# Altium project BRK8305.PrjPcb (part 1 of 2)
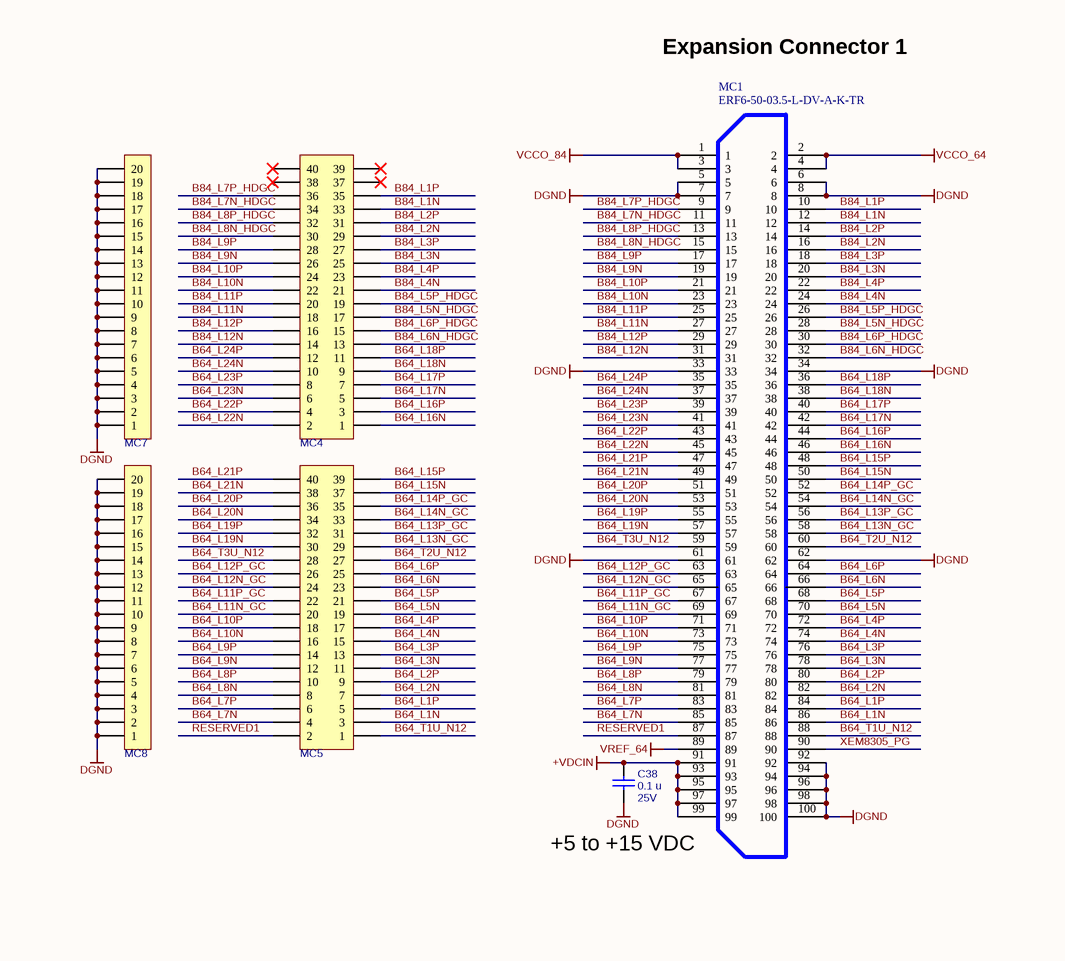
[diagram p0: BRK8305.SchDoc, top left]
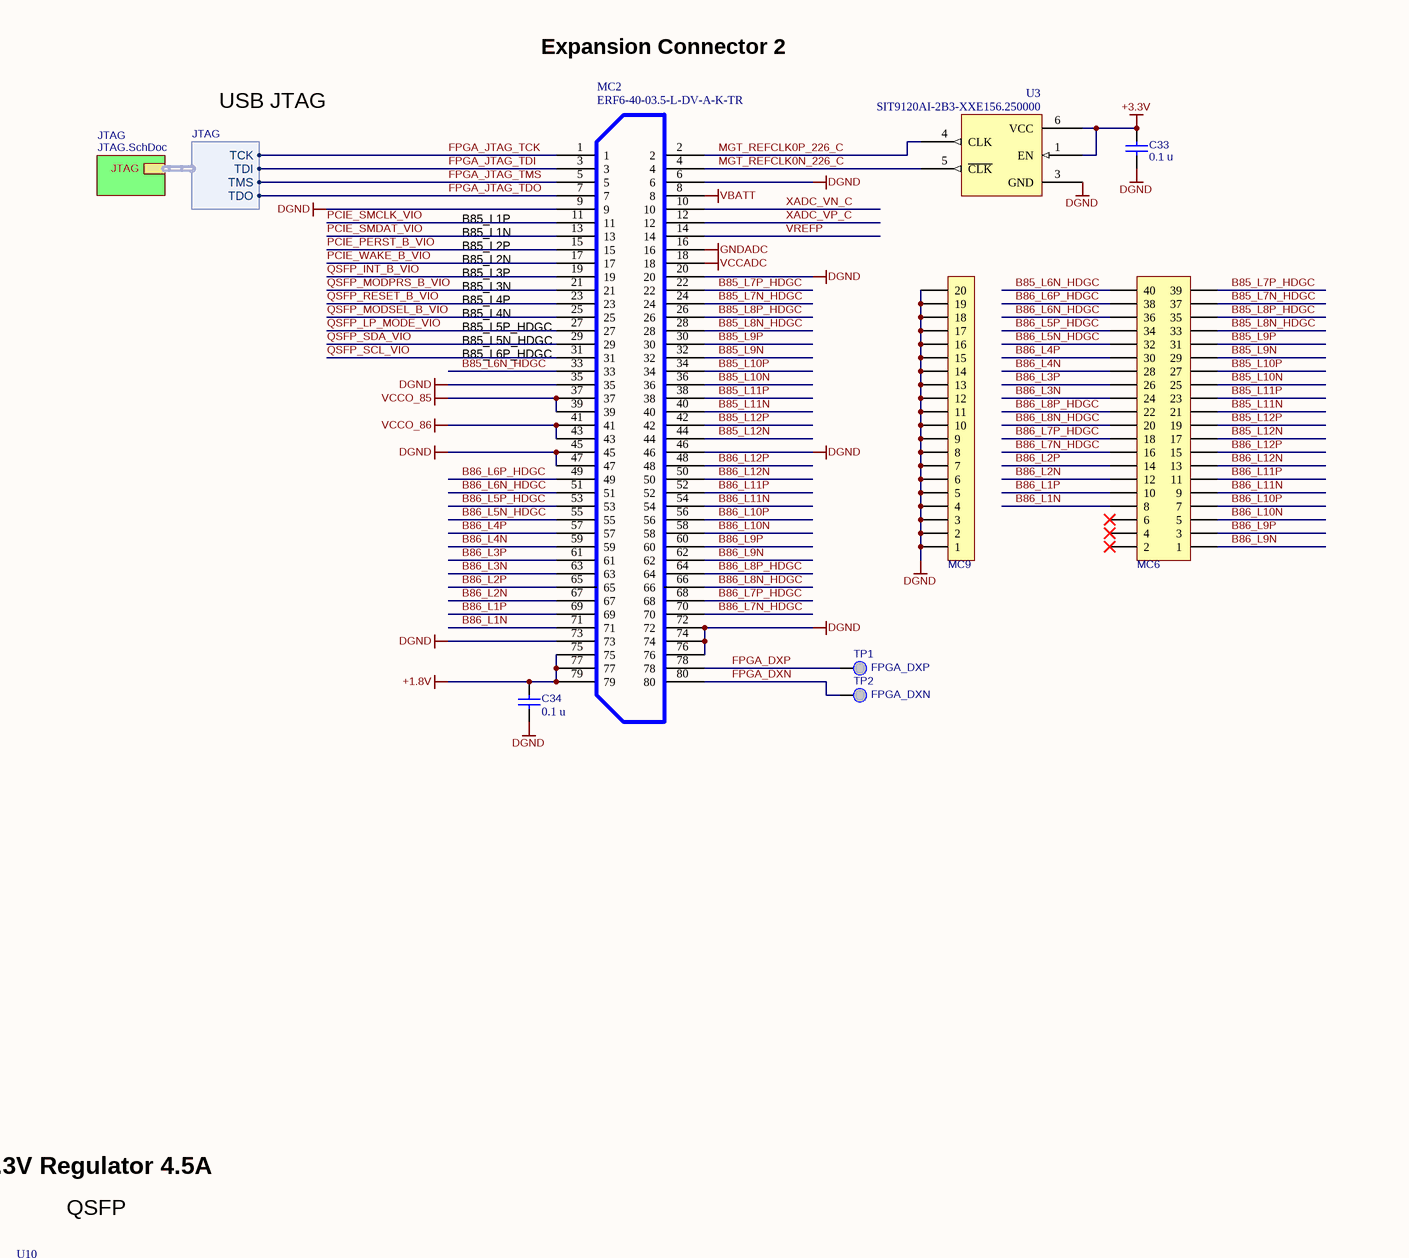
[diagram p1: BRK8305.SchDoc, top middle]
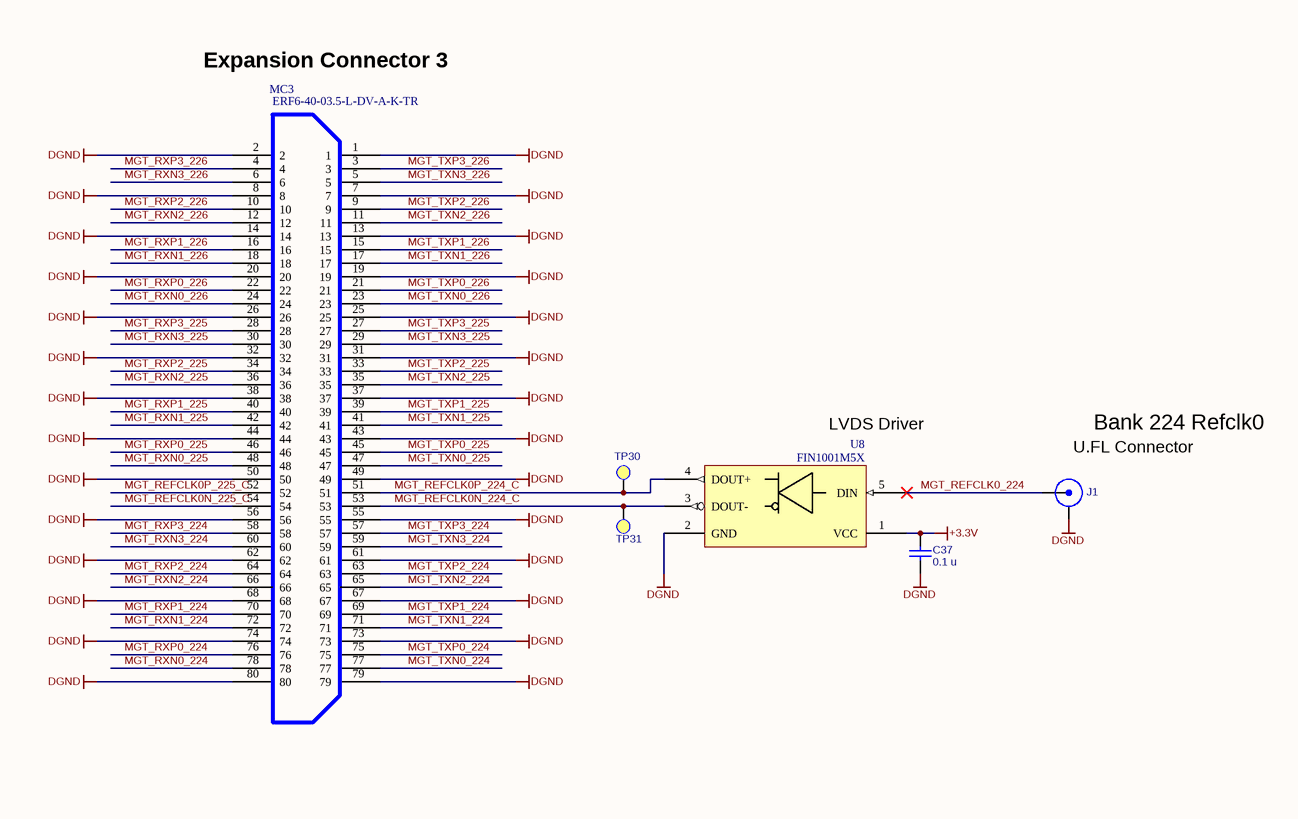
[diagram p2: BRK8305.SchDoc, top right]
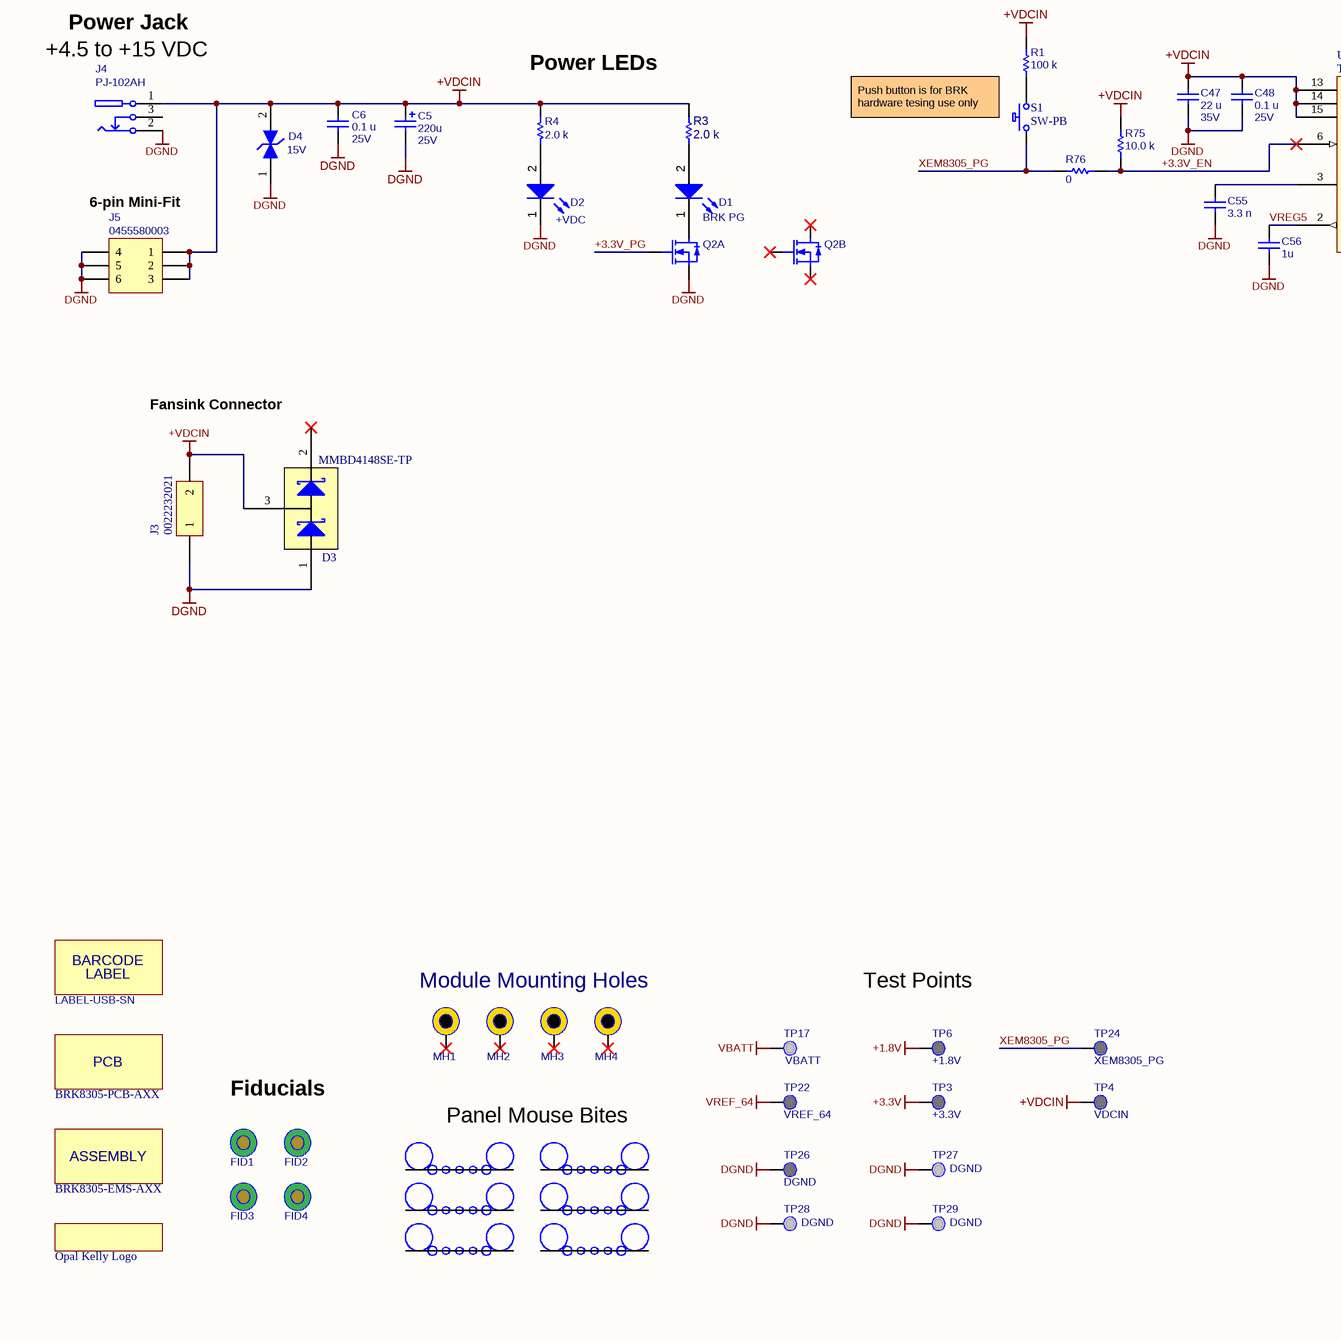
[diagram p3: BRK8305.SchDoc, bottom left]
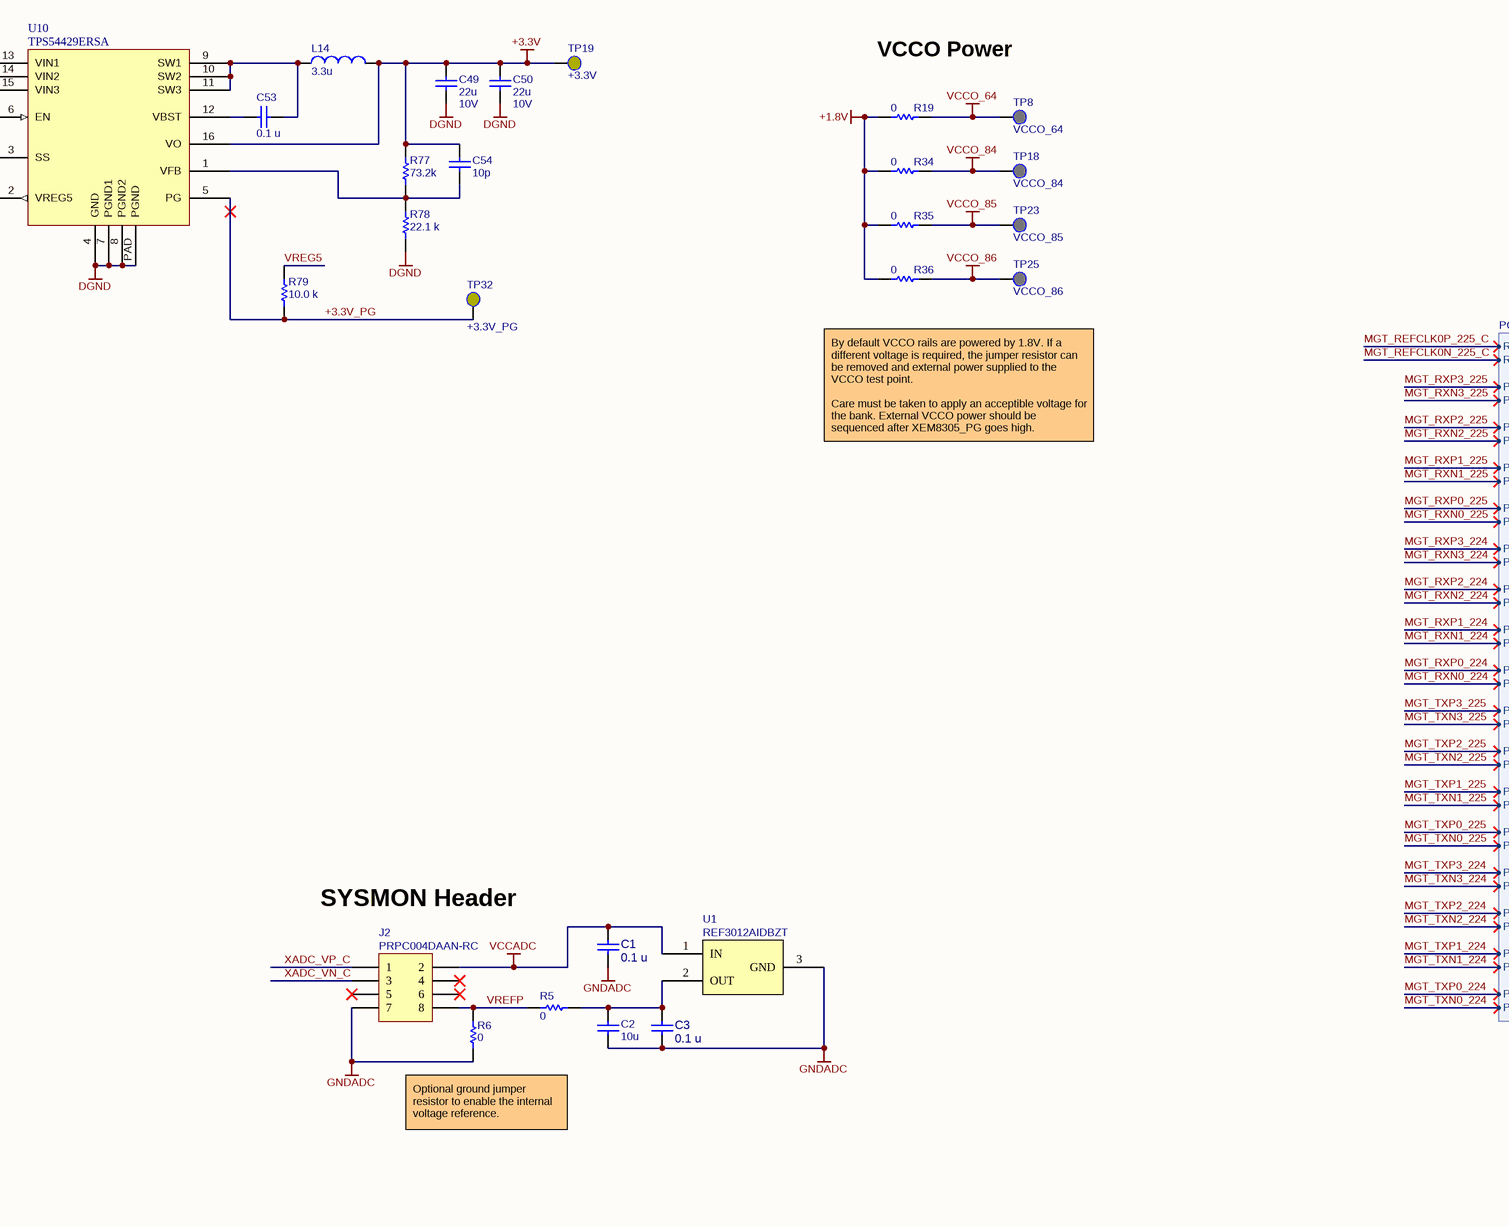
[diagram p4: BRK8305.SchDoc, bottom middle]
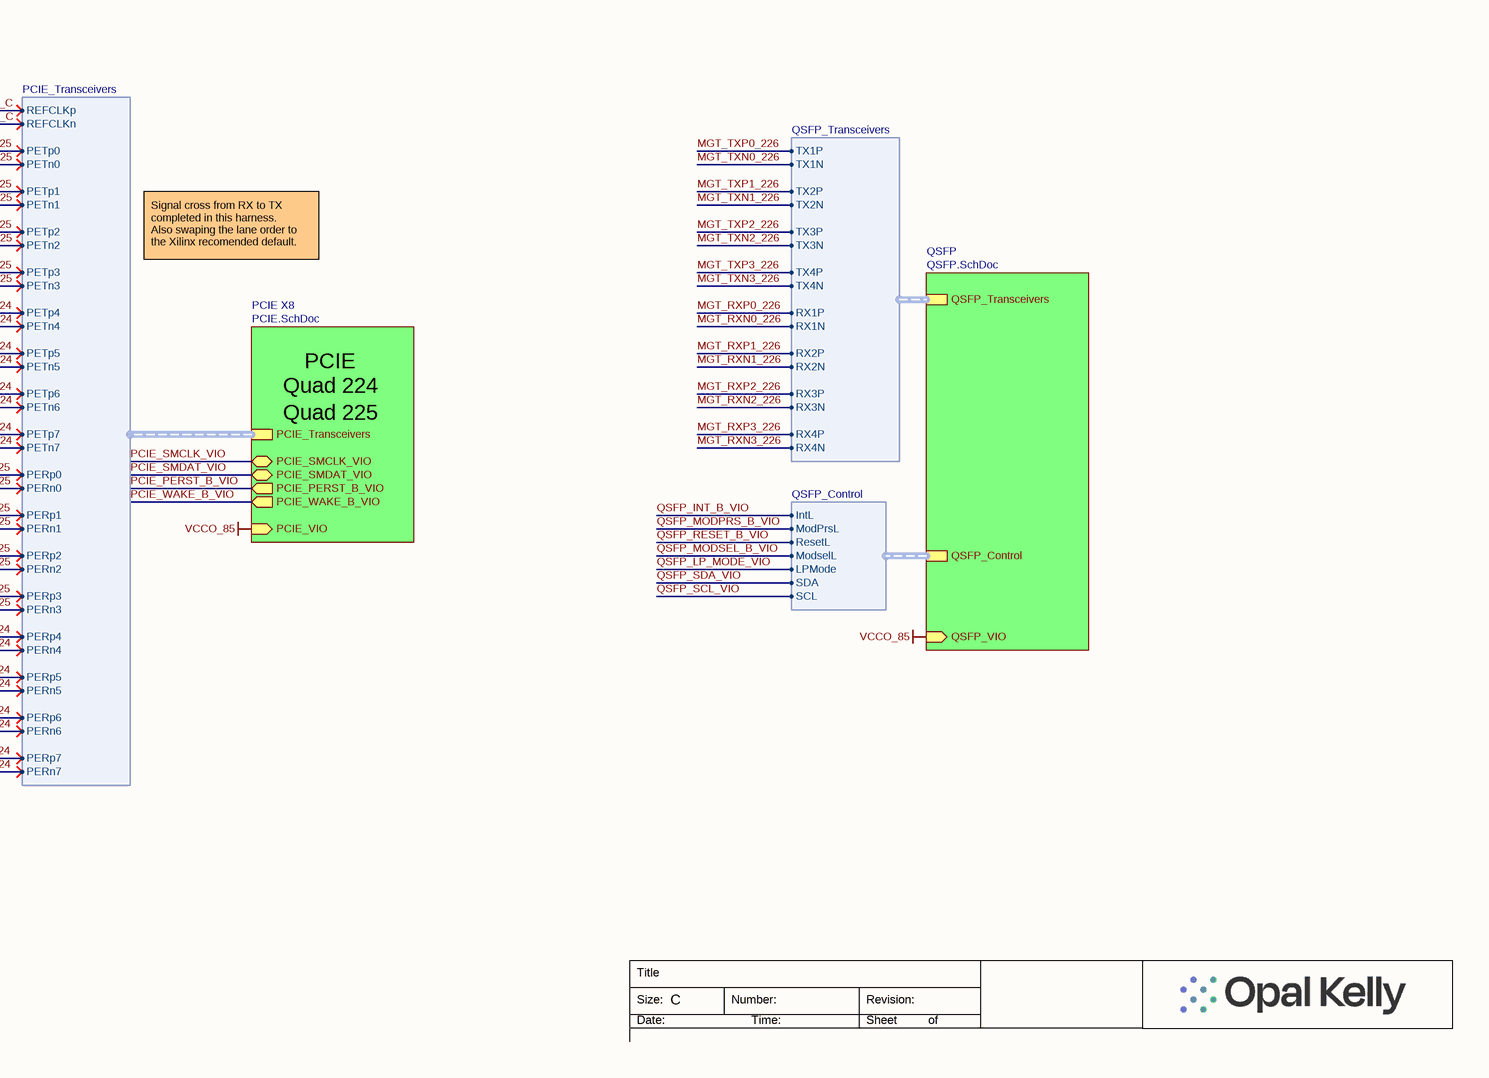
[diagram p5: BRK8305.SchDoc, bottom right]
PCB_Revision: A; Part_Number: BRK8305; BOM_Revision: 03
4 sheets, 240 parts. Net scope: hierarchical (ports join the sheet entries above them; power ports are global).
Board file: BRK8305.PcbDoc
Sheets:
  BRK8305.SchDoc
    PCIE X8 = PCIE.SchDoc
    QSFP = QSFP.SchDoc
    JTAG = JTAG.SchDoc

## Sheet BRK8305.SchDoc: BRK8305 PCB
size D; Author: Ray Anderson; Organization: Opal Kelly; Address1: 13500 SW 72nd Ave, STE 100; Address2: Portland, OR 97223; Address3: 217.391.3724; Address4: http://www.opalkelly.com; DocumentNumber: 1; Revision: 1; SheetNumber: 1; SheetTotal: 3

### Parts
*  Opal Kelly Logo  [okLogo-23x5-2021]
ASSY1  BRK8305-EMS-AXX  (mechanical)
C1  value 0.1 u  [CAPC1005X06A]  (hidden comment: C0402C104K8PACTU)
C2  value 10u  [CAPC1005X06A]  (hidden comment: GRM155C80J106ME11D)
C3  value 0.1 u  [CAPC1005X06A]  (hidden comment: C0402C104K8PACTU)
C5  value 220u  Voltage: 25V  [CAPAE9083X70N]  (hidden comment: EEE-FK1E221P)
C6  value 0.1 u  Voltage: 25V  [CAPC1005X06A]  (hidden comment: TMK105BJ104KV-F)
C33  value 0.1 u  [CAPC1005X06A]  (hidden comment: C0402C104K8PACTU)
C34  value 0.1 u  [CAPC1005X06A]  (hidden comment: C0402C104K8PACTU)
C37  value 0.1 u  [CAPC1005X06A]  (hidden comment: SM-0402, 10%, 10v)
C38  value 0.1 u  Voltage: 25V  [CAPC1005X06A]  (hidden comment: TMK105BJ104KV-F)
C47  value 22 u  Voltage: 35V  [CAPC3216N]  (hidden comment: C3216X5R1V226M160AC)
C48  value 0.1 u  Voltage: 25V  [CAPC1005X06A]  (hidden comment: TMK105BJ104KV-F)
C49  value 22u  Voltage: 10V  [CAPC3216N]  (hidden comment: LMK316AB7226KL-TR)
C50  value 22u  Voltage: 10V  [CAPC3216N]  (hidden comment: LMK316AB7226KL-TR)
C53  value 0.1 u  [CAPC1005X06A]  (hidden comment: C0402C104K8PACTU)
C54  value 10p  [CAPC1005X06A]  (hidden comment: CBR04C100J5GAC)
C55  value 3.3 n  [CAPC1005X06A]  (hidden comment: C0402C332K5RACTU)
C56  value 1u  [CAPC1005X06A]  (hidden comment: LMK105BJ105KV-F)
D1  BRK PG  [CD1608-0603-PIN1-CATHODE]
D2  +VDC  [CD1608-0603-PIN1-CATHODE]
D3  MMBD4148SE-TP  [SOT23-95P240X110]
D4  Voltage: 15V  [DO-214AA]  (hidden comment: D ESD)
FID1  FIDUCIAL  [FID1MM/2MM-SS]  (value not drawn)
FID2  FIDUCIAL  [FID1MM/2MM-SS]  (value not drawn)
FID3  FIDUCIAL  [FID1MM/2MM-SS]  (value not drawn)
FID4  FIDUCIAL  [FID1MM/2MM-SS]  (value not drawn)
J1  RXP0  [UFL-R-SMT-1]  (value not drawn)
J2  PRPC004DAAN-RC  [HDR2X4]
J3  0022232021  [MOLEX-0022232021]
J4  PJ-102AH  [CUI-PJ102A]
J5  0455580003  [0455580003]
L14  value 3.3u  [1267AY]  (hidden comment: 1267AY-3R3N=P3)
LABEL1  LABEL-USB-SN  (mechanical)
MB1  PCB Array Mouse Bite  [MouseBite-01]  (value not drawn)
MB2  PCB Array Mouse Bite  [MouseBite-01]  (value not drawn)
MB3  PCB Array Mouse Bite  [MouseBite-01]  (value not drawn)
MB4  PCB Array Mouse Bite  [MouseBite-01]  (value not drawn)
MB5  PCB Array Mouse Bite  [MouseBite-01]  (value not drawn)
MB6  PCB Array Mouse Bite  [MouseBite-01]  (value not drawn)
MC1  ERF6-50-03.5-L-DV-A-K-TR  [ERF6-50-03.5-L-DV-A-K-TR]
MC2  ERF6-40-03.5-L-DV-A-K-TR  [ERF6-40-03.5-L-DV-A-K-TR]
MC3  ERF6-40-03.5-L-DV-A-K-TR  [ERF6-40-03.5-L-DV-A-K-TR]
MC4  0877584016  [HDR2X20-2MM]  (value not drawn)
MC5  0877584016  [HDR2X20-2MM]  (value not drawn)
MC6  0877584016  [HDR2X20-2MM]  (value not drawn)
MC7  Header, 20-Pin, Single Row  [HDR1X20-2MM]  (value not drawn)
MC8  Header, 20-Pin, Single Row  [HDR1X20-2MM]  (value not drawn)
MC9  Header, 20-Pin, Single Row  [HDR1X20-2MM]  (value not drawn)
MH1  MTG  [MTG-3.2/6.5-PTH]  (value not drawn)
MH2  MTG  [MTG-3.2/6.5-PTH]  (value not drawn)
MH3  MTG  [MTG-3.2/6.5-PTH]  (value not drawn)
MH4  MTG  [MTG-3.2/6.5-PTH]  (value not drawn)
PCB1  BRK8305-PCB-AXX  (mechanical)
Q2  SI1922EDH-T1-GE3  [SOT363-6N]  (value not drawn)  (parts A,B of 2)
R1  value 100 k  [RESC1005X06A]  (hidden comment: CRCW0402100KFKED)
R3  value 2.0 k  [RESC1005X06A]  (hidden comment: CRCW04022K00FKED)
R4  value 2.0 k  [RESC1005X06A]  (hidden comment: CRCW04022K00FKED)
R5  value 0  [RESC1608N]  (hidden comment: CRCW06030000Z0EA)
R6  value 0  [RESC1608N]  (hidden comment: CRCW06030000Z0EA)
R19  value 0  [RESC1608N]  (hidden comment: CRCW06030000Z0EA)
R34  value 0  [RESC1608N]  (hidden comment: CRCW06030000Z0EA)
R35  value 0  [RESC1608N]  (hidden comment: CRCW06030000Z0EA)
R36  value 0  [RESC1608N]  (hidden comment: CRCW06030000Z0EA)
R75  value 10.0 k  [RESC1005X06A]  (hidden comment: CRCW040210K0FKED)
R76  value 0  [RESC1005X06A]  (hidden comment: CRCW04020000Z0ED)
R77  value 73.2k  [RESC1005X06A]  (hidden comment: CRCW040273K2FKED)
R78  value 22.1 k  [RESC1005X06A]  (hidden comment: CRCW040222K1FKEDC)
R79  value 10.0 k  [RESC1005X06A]  (hidden comment: CRCW040210K0FKED)
S1  SW-PB  [Switch-PCB-wMounts]
TP1  FPGA_DXP  [TP-PTH-25/45]
TP2  FPGA_DXN  [TP-PTH-25/45]
TP3  +3.3V  [TP-PTH-65/100]
TP4  VDCIN  [TP-PTH-65/100]
TP6  +1.8V  [TP-PTH-65/100]
TP8  VCCO_64  [TP-PTH-65/100]
TP17  VBATT  [TP-PTH-25/45]
TP18  VCCO_84  [TP-PTH-65/100]
TP19  +3.3V  [TP-SMD40]
TP22  VREF_64  [TP-PTH-65/100]
TP23  VCCO_85  [TP-PTH-65/100]
TP24  XEM8305_PG  [TP-PTH-65/100]
TP25  VCCO_86  [TP-PTH-65/100]
TP26  DGND  [TP-PTH-65/100]
TP27  DGND  [TP-PTH-25/45]
TP28  DGND  [TP-PTH-25/45]
TP29  DGND  [TP-PTH-25/45]
TP30  TESTPOINT-SMD20  [TP-SMD20]  (value not drawn)
TP31  TESTPOINT-SMD20  [TP-SMD20]  (value not drawn)
TP32  +3.3V_PG  [TP-SMD40]
U1  REF3012AIDBZT  [SOT23-95P240X110]
U3  SIT9120AI-2B3-XXE156.250000  [SIT9120AX-XB]
U8  FIN1001M5X  [SOT23-5]
U10  TPS54429ERSA  [TPS54429E]

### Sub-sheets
JTAG = JTAG.SchDoc: JTAG (harness JTAG)
PCIE X8 = PCIE.SchDoc: PCIE_Transceivers (harness PCIE_Transceivers), PCIE_SMCLK_VIO (bidir), PCIE_WAKE_B_VIO (out), PCIE_SMDAT_VIO (bidir), PCIE_PERST_B_VIO (out), PCIE_VIO (in)
QSFP = QSFP.SchDoc: QSFP_Control (harness QSFP_Control), QSFP_Transceivers (harness QSFP_Transceivers), QSFP_VIO (in)

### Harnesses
PCIE_Transceivers: PETn3, PETp3, PERn3, PERp3, PETn2, PETp2, PERn2, PERp2, PETn1, PETp1, PERn1, PERp1, PETn0, PETp0, PERn0, PERp0, PETn4, PETp4, PERn4, PERp4, PETn5, PETp5, PERn5, PERp5, PETn6, PETp6, PERn6, PERp6, PETn7, PETp7, PERn7, PERp7, REFCLKn, REFCLKp
QSFP_Transceivers: TX1P, TX1N, TX2P, TX2N, TX3P, TX3N, TX4P, TX4N, RX1P, RX1N, RX2P, RX2N, RX3P, RX3N, RX4P, RX4N
QSFP_Control: ModPrsL, IntL, LPMode, ModselL, ResetL, SCL, SDA
JTAG: TDI, TDO, TCK, TMS

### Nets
+1.8V: C34.2 MC2.75 MC2.77 MC2.79 R19.1 R34.1 R35.1 R36.1 TP6.1(PIN)
+3.3V: C33.2 C37.2 C49.2 C50.2 C54.2 L14.2 R77.2 TP3.1(PIN) TP19.1(PIN) U3.1(EN) U3.6(VCC) U8.1(VCC) U10.16(VO)
+VDCIN: C5.1 C6.2 C38.2 C47.2 C48.2 D3.3 D4.2(K) J3.2 J4.1 J5.1 J5.2 J5.3 MC1.91 MC1.93 MC1.95 MC1.97 MC1.99 R1.2 R3.2 R4.2 R75.2 TP4.1(PIN) U10.13(VIN1) U10.14(VIN2) U10.15(VIN3)
DGND: C5.2 C6.1 C33.1 C34.1 C37.1 C38.1 C47.1 C48.1 C49.1 C50.1 C55.1 C56.1 D2.1(K) D3.1 D4.1(A) J1.2(GND) J3.1 J4.2 J5.4 J5.5 J5.6 MC1.5 MC1.6 MC1.7 MC1.8 MC1.33 MC1.34 MC1.61 MC1.62 MC1.92 MC1.94 MC1.96 MC1.98 MC1.100 MC2.6 MC2.9 MC2.20 MC2.35 MC2.45 MC2.46 MC2.47 MC2.72 MC2.73 MC2.74 MC2.76 MC3.1 MC3.2 MC3.7 MC3.8 MC3.13 MC3.14 MC3.19 MC3.20 MC3.25 MC3.26 MC3.31 MC3.32 MC3.37 MC3.38 MC3.43 MC3.44 MC3.49 MC3.50 MC3.55 MC3.56 MC3.61 MC3.62 MC3.67 MC3.68 MC3.73 MC3.74 MC3.79 MC3.80 MC7.1 MC7.2 MC7.3 MC7.4 MC7.5 MC7.6 MC7.7 MC7.8 MC7.9 MC7.10 MC7.11 MC7.12 MC7.13 MC7.14 MC7.15 MC7.16 MC7.17 MC7.18 MC7.19 MC7.20 MC8.1 MC8.2 MC8.3 MC8.4 MC8.5 MC8.6 MC8.7 MC8.8 MC8.9 MC8.10 MC8.11 MC8.12 MC8.13 MC8.14 MC8.15 MC8.16 MC8.17 MC8.18 MC8.19 MC8.20 MC9.1 MC9.2 MC9.3 MC9.4 MC9.5 MC9.6 MC9.7 MC9.8 MC9.9 MC9.10 MC9.11 MC9.12 MC9.13 MC9.14 MC9.15 MC9.16 MC9.17 MC9.18 MC9.19 MC9.20 Q2.1(S1) R78.1 TP26.1(PIN) TP27.1(PIN) TP28.1(PIN) TP29.1(PIN) U3.3(GND) U8.2(GND) U10.4(GND) U10.7(PGND1) U10.8(PGND2) U10.PAD(PGND)
GNDADC: C1.2 C2.1 C3.2 J2.7 MC2.16 R6.1 U1.3(GND)
VBATT: MC2.8 TP17.1(PIN)
VCCADC: C1.1 J2.2 MC2.18 U1.1(IN)
VCCO_64: MC1.2 MC1.4 R19.2 TP8.1(PIN)
VCCO_84: MC1.1 MC1.3 R34.2 TP18.1(PIN)
VCCO_85: MC2.37 MC2.39 R35.2 TP23.1(PIN) ; sheet PCIE X8/PCIE_VIO, sheet QSFP/QSFP_VIO
VCCO_86: MC2.41 MC2.43 R36.2 TP25.1(PIN)
VREF_64: MC1.89 TP22.1(PIN)
+3.3V_EN: R75.1 R76.1 U10.6(EN)
+3.3V_PG: Q2.2(G1) R79.1 TP32.1(PIN) U10.5(PG)
B64_L1N: MC1.86 MC5.3
B64_L1P: MC1.84 MC5.5
B64_L2N: MC1.82 MC5.7
B64_L2P: MC1.80 MC5.9
B64_L3N: MC1.78 MC5.11
B64_L3P: MC1.76 MC5.13
B64_L4N: MC1.74 MC5.15
B64_L4P: MC1.72 MC5.17
B64_L5N: MC1.70 MC5.19
B64_L5P: MC1.68 MC5.21
B64_L6N: MC1.66 MC5.23
B64_L6P: MC1.64 MC5.25
B64_L7N: MC1.85 MC5.4
B64_L7P: MC1.83 MC5.6
B64_L8N: MC1.81 MC5.8
B64_L8P: MC1.79 MC5.10
B64_L9N: MC1.77 MC5.12
B64_L9P: MC1.75 MC5.14
B64_L10N: MC1.73 MC5.16
B64_L10P: MC1.71 MC5.18
B64_L11N_GC: MC1.69 MC5.20
B64_L11P_GC: MC1.67 MC5.22
B64_L12N_GC: MC1.65 MC5.24
B64_L12P_GC: MC1.63 MC5.26
B64_L13N_GC: MC1.58 MC5.29
B64_L13P_GC: MC1.56 MC5.31
B64_L14N_GC: MC1.54 MC5.33
B64_L14P_GC: MC1.52 MC5.35
B64_L15N: MC1.50 MC5.37
B64_L15P: MC1.48 MC5.39
B64_L16N: MC1.46 MC4.1
B64_L16P: MC1.44 MC4.3
B64_L17N: MC1.42 MC4.5
B64_L17P: MC1.40 MC4.7
B64_L18N: MC1.38 MC4.9
B64_L18P: MC1.36 MC4.11
B64_L19N: MC1.57 MC5.30
B64_L19P: MC1.55 MC5.32
B64_L20N: MC1.53 MC5.34
B64_L20P: MC1.51 MC5.36
B64_L21N: MC1.49 MC5.38
B64_L21P: MC1.47 MC5.40
B64_L22N: MC1.45 MC4.2
B64_L22P: MC1.43 MC4.4
B64_L23N: MC1.41 MC4.6
B64_L23P: MC1.39 MC4.8
B64_L24N: MC1.37 MC4.10
B64_L24P: MC1.35 MC4.12
B64_T1U_N12: MC1.88 MC5.1
B64_T2U_N12: MC1.60 MC5.27
B64_T3U_N12: MC1.59 MC5.28
B84_L1N: MC1.12 MC4.33
B84_L1P: MC1.10 MC4.35
B84_L2N: MC1.16 MC4.29
B84_L2P: MC1.14 MC4.31
B84_L3N: MC1.20 MC4.25
B84_L3P: MC1.18 MC4.27
B84_L4N: MC1.24 MC4.21
B84_L4P: MC1.22 MC4.23
B84_L5N_HDGC: MC1.28 MC4.17
B84_L5P_HDGC: MC1.26 MC4.19
B84_L6N_HDGC: MC1.32 MC4.13
B84_L6P_HDGC: MC1.30 MC4.15
B84_L7N_HDGC: MC1.11 MC4.34
B84_L7P_HDGC: MC1.9 MC4.36
B84_L8N_HDGC: MC1.15 MC4.30
B84_L8P_HDGC: MC1.13 MC4.32
B84_L9N: MC1.19 MC4.26
B84_L9P: MC1.17 MC4.28
B84_L10N: MC1.23 MC4.22
B84_L10P: MC1.21 MC4.24
B84_L11N: MC1.27 MC4.18
B84_L11P: MC1.25 MC4.20
B84_L12N: MC1.31 MC4.14
B84_L12P: MC1.29 MC4.16
B85_L6N_HDGC: MC2.33 MC6.40
B85_L7N_HDGC: MC2.24 MC6.37
B85_L7P_HDGC: MC2.22 MC6.39
B85_L8N_HDGC: MC2.28 MC6.33
B85_L8P_HDGC: MC2.26 MC6.35
B85_L9N: MC2.32 MC6.29
B85_L9P: MC2.30 MC6.31
B85_L10N: MC2.36 MC6.25
B85_L10P: MC2.34 MC6.27
B85_L11N: MC2.40 MC6.21
B85_L11P: MC2.38 MC6.23
B85_L12N: MC2.44 MC6.17
B85_L12P: MC2.42 MC6.19
B86_L1N: MC2.71 MC6.8
B86_L1P: MC2.69 MC6.10
B86_L2N: MC2.67 MC6.12
B86_L2P: MC2.65 MC6.14
B86_L3N: MC2.63 MC6.24
B86_L3P: MC2.61 MC6.26
B86_L4N: MC2.59 MC6.28
B86_L4P: MC2.57 MC6.30
B86_L5N_HDGC: MC2.55 MC6.32
B86_L5P_HDGC: MC2.53 MC6.34
B86_L6N_HDGC: MC2.51 MC6.36
B86_L6P_HDGC: MC2.49 MC6.38
B86_L7N_HDGC: MC2.70 MC6.16
B86_L7P_HDGC: MC2.68 MC6.18
B86_L8N_HDGC: MC2.66 MC6.20
B86_L8P_HDGC: MC2.64 MC6.22
B86_L9N: MC2.62 MC6.1
B86_L9P: MC2.60 MC6.3
B86_L10N: MC2.58 MC6.5
B86_L10P: MC2.56 MC6.7
B86_L11N: MC2.54 MC6.9
B86_L11P: MC2.52 MC6.11
B86_L12N: MC2.50 MC6.13
B86_L12P: MC2.48 MC6.15
FPGA_DXN: MC2.80 TP2.1(PIN)
FPGA_DXP: MC2.78 TP1.1(PIN)
FPGA_JTAG_TCK: MC2.1 ; sheet JTAG/JTAG.TCK
FPGA_JTAG_TDI: MC2.3 ; sheet JTAG/JTAG.TDI
FPGA_JTAG_TDO: MC2.7 ; sheet JTAG/JTAG.TDO
FPGA_JTAG_TMS: MC2.5 ; sheet JTAG/JTAG.TMS
MGT_REFCLK0_224: J1.1(SIGNAL) U8.5(DIN)
MGT_REFCLK0N_224_C: MC3.53 TP31.1(PIN) U8.3(DOUT-)
MGT_REFCLK0N_225_C: MC3.54 ; sheet PCIE X8/PCIE_Transceivers.REFCLKn
MGT_REFCLK0N_226_C: MC2.4 U3.5(~{CLK})
MGT_REFCLK0P_224_C: MC3.51 TP30.1(PIN) U8.4(DOUT+)
MGT_REFCLK0P_225_C: MC3.52 ; sheet PCIE X8/PCIE_Transceivers.REFCLKp
MGT_REFCLK0P_226_C: MC2.2 U3.4(CLK)
MGT_RXN0_224: MC3.78 ; sheet PCIE X8/PCIE_Transceivers.PETn7
MGT_RXN0_225: MC3.48 ; sheet PCIE X8/PCIE_Transceivers.PETn3
MGT_RXN0_226: MC3.24 ; sheet QSFP/QSFP_Transceivers.RX1N
MGT_RXN1_224: MC3.72 ; sheet PCIE X8/PCIE_Transceivers.PETn6
MGT_RXN1_225: MC3.42 ; sheet PCIE X8/PCIE_Transceivers.PETn2
MGT_RXN1_226: MC3.18 ; sheet QSFP/QSFP_Transceivers.RX2N
MGT_RXN2_224: MC3.66 ; sheet PCIE X8/PCIE_Transceivers.PETn5
MGT_RXN2_225: MC3.36 ; sheet PCIE X8/PCIE_Transceivers.PETn1
MGT_RXN2_226: MC3.12 ; sheet QSFP/QSFP_Transceivers.RX3N
MGT_RXN3_224: MC3.60 ; sheet PCIE X8/PCIE_Transceivers.PETn4
MGT_RXN3_225: MC3.30 ; sheet PCIE X8/PCIE_Transceivers.PETn0
MGT_RXN3_226: MC3.6 ; sheet QSFP/QSFP_Transceivers.RX4N
MGT_RXP0_224: MC3.76 ; sheet PCIE X8/PCIE_Transceivers.PETp7
MGT_RXP0_225: MC3.46 ; sheet PCIE X8/PCIE_Transceivers.PETp3
MGT_RXP0_226: MC3.22 ; sheet QSFP/QSFP_Transceivers.RX1P
MGT_RXP1_224: MC3.70 ; sheet PCIE X8/PCIE_Transceivers.PETp6
MGT_RXP1_225: MC3.40 ; sheet PCIE X8/PCIE_Transceivers.PETp2
MGT_RXP1_226: MC3.16 ; sheet QSFP/QSFP_Transceivers.RX2P
MGT_RXP2_224: MC3.64 ; sheet PCIE X8/PCIE_Transceivers.PETp5
MGT_RXP2_225: MC3.34 ; sheet PCIE X8/PCIE_Transceivers.PETp1
MGT_RXP2_226: MC3.10 ; sheet QSFP/QSFP_Transceivers.RX3P
MGT_RXP3_224: MC3.58 ; sheet PCIE X8/PCIE_Transceivers.PETp4
MGT_RXP3_225: MC3.28 ; sheet PCIE X8/PCIE_Transceivers.PETp0
MGT_RXP3_226: MC3.4 ; sheet QSFP/QSFP_Transceivers.RX4P
MGT_TXN0_224: MC3.77 ; sheet PCIE X8/PCIE_Transceivers.PERn7
MGT_TXN0_225: MC3.47 ; sheet PCIE X8/PCIE_Transceivers.PERn3
MGT_TXN0_226: MC3.23 ; sheet QSFP/QSFP_Transceivers.TX1N
MGT_TXN1_224: MC3.71 ; sheet PCIE X8/PCIE_Transceivers.PERn6
MGT_TXN1_225: MC3.41 ; sheet PCIE X8/PCIE_Transceivers.PERn2
MGT_TXN1_226: MC3.17 ; sheet QSFP/QSFP_Transceivers.TX2N
MGT_TXN2_224: MC3.65 ; sheet PCIE X8/PCIE_Transceivers.PERn5
MGT_TXN2_225: MC3.35 ; sheet PCIE X8/PCIE_Transceivers.PERn1
MGT_TXN2_226: MC3.11 ; sheet QSFP/QSFP_Transceivers.TX3N
MGT_TXN3_224: MC3.59 ; sheet PCIE X8/PCIE_Transceivers.PERn4
MGT_TXN3_225: MC3.29 ; sheet PCIE X8/PCIE_Transceivers.PERn0
MGT_TXN3_226: MC3.5 ; sheet QSFP/QSFP_Transceivers.TX4N
MGT_TXP0_224: MC3.75 ; sheet PCIE X8/PCIE_Transceivers.PERp7
MGT_TXP0_225: MC3.45 ; sheet PCIE X8/PCIE_Transceivers.PERp3
MGT_TXP0_226: MC3.21 ; sheet QSFP/QSFP_Transceivers.TX1P
MGT_TXP1_224: MC3.69 ; sheet PCIE X8/PCIE_Transceivers.PERp6
MGT_TXP1_225: MC3.39 ; sheet PCIE X8/PCIE_Transceivers.PERp2
MGT_TXP1_226: MC3.15 ; sheet QSFP/QSFP_Transceivers.TX2P
MGT_TXP2_224: MC3.63 ; sheet PCIE X8/PCIE_Transceivers.PERp5
MGT_TXP2_225: MC3.33 ; sheet PCIE X8/PCIE_Transceivers.PERp1
MGT_TXP2_226: MC3.9 ; sheet QSFP/QSFP_Transceivers.TX3P
MGT_TXP3_224: MC3.57 ; sheet PCIE X8/PCIE_Transceivers.PERp4
MGT_TXP3_225: MC3.27 ; sheet PCIE X8/PCIE_Transceivers.PERp0
MGT_TXP3_226: MC3.3 ; sheet QSFP/QSFP_Transceivers.TX4P
PCIE_PERST_B_VIO: MC2.15 ; sheet PCIE X8/PCIE_PERST_B_VIO
PCIE_SMCLK_VIO: MC2.11 ; sheet PCIE X8/PCIE_SMCLK_VIO
PCIE_SMDAT_VIO: MC2.13 ; sheet PCIE X8/PCIE_SMDAT_VIO
PCIE_WAKE_B_VIO: MC2.17 ; sheet PCIE X8/PCIE_WAKE_B_VIO
QSFP_INT_B_VIO: MC2.19 ; sheet QSFP/QSFP_Control.IntL
QSFP_LP_MODE_VIO: MC2.27 ; sheet QSFP/QSFP_Control.LPMode
QSFP_MODPRS_B_VIO: MC2.21 ; sheet QSFP/QSFP_Control.ModPrsL
QSFP_MODSEL_B_VIO: MC2.25 ; sheet QSFP/QSFP_Control.ModselL
QSFP_RESET_B_VIO: MC2.23 ; sheet QSFP/QSFP_Control.ResetL
QSFP_SCL_VIO: MC2.31 ; sheet QSFP/QSFP_Control.SCL
QSFP_SDA_VIO: MC2.29 ; sheet QSFP/QSFP_Control.SDA
RESERVED1: MC1.87 MC5.2
VREFP: J2.8 MC2.14 R5.2 R6.2
VREG5: C56.2 R79.2 U10.2(VREG5)
XADC_VN_C: J2.3 MC2.10
XADC_VP_C: J2.1 MC2.12
XEM8305_PG: MC1.90 R76.2 S1.1 TP24.1(PIN)
NetC2_2: C2.2 C3.1 R5.1 U1.2(OUT)
NetC53_1: C53.1 U10.12(VBST)
NetC53_2: C53.2 L14.1 U10.9(SW1) U10.10(SW2) U10.11(SW3)
NetC54_1: C54.1 R77.1 R78.2 U10.1(VFB)
NetC55_2: C55.2 U10.3(SS)
NetD1_1: D1.1(K) Q2.6(D1)
NetD1_2: D1.2(A) R3.1
NetD2_2: D2.2(A) R4.1
NetR1_1: R1.1 S1.2

Not connected (* = marked no-connect by the designer): D3 2*; J2 4* 5* 6*; J4 3; MC4 37* 38* 39* 40*; MC6 2* 4* 6*; MH1 1*; MH2 1*; MH3 1*; MH4 1*; Q2 3(D2)* 4(S2)* 5(G2)*

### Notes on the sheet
- Expansion Connector 1
- Expansion Connector 2
- Expansion Connector 3
- USB JTAG
- (near MC2) B85_L1P
  B85_L1N
  B85_L2P
  B85_L2N
  B85_L3P
  B85_L3N
  B85_L4P
  B85_L4N
  B85_L5P_HDGC
  B85_L5N_HDGC
  B85_L6P_HDGC
- (near U8) LVDS Driver
- (near J1) U.FL Connector
- Bank 224 Refclk0
- +5 to +15 VDC
- 3.3V Regulator 4.5A
- QSFP
- Power Jack
- (near J4) +4.5 to +15 VDC
- Power LEDs
- VCCO Power
- Push button is for BRK hardware tesing use only
- 6-pin Mini-Fit
- Fansink Connector
- By default VCCO rails are powered by 1.8V. If a different voltage is required, the jumper resistor can be removed and external power supplied to the VCCO test point.
  Care must be taken to apply an acceptible voltage for the bank. External VCCO power should be sequenced after XEM8305_PG goes high.
- Signal cross from RX to TX completed in this harness.
  Also swaping the lane order to the Xilinx recomended default.
- Quad 224
- Quad 225
- PCIE
- SYSMON Header
- Module Mounting Holes
- Test Points
- Fiducials
- (near MB2) Panel Mouse Bites
- (near R6) Optional ground jumper resistor to enable the internal voltage reference.
- Title
- Size:
- Date:
- C
- Number:
- Time:
- Revision:
- Sheet
- of

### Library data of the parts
* = OKLOGO: partnumber: ALIGNI_IGNORE
ASSY1 = 002591: BRK8305 PCB assembly; Partnumber: 002591; Manufacturer: PCB Assembly Cost
C1 C3 = 000070: Ceramic capacitor; Manufacturer: Kemet; partnumber: 000070; Description 2: SM-0402, 10%, 10v; ValueFloat: 1E-7; Tolerance (%): 10
C2 = 001983: Ceramic capacitor; Partnumber: 001983; Manufacturer: Murata; ValueFloat: 1E-5; Tolerance (%): 20; Description 2: 0402, 6.3V
C5 = 001532: Polarized; Partnumber: 001532; manufacturer: Panasonic; ValueFloat: 0.00022; id: 155442; inventory_price: 0.2; x_tolerance: 20; x_voltage-rating: 25
C6 C38 = 001073: Ceramic capacitor; Manufacturer: Taiyo Yuden; partnumber: 001073; Description 2: 0402, 25V; ValueFloat: 1E-7; Tolerance (%): 10
C33 C53 = 000070: Partnumber: 000070; manufacturer: Kemet; ValueFloat: 1E-7; x_tolerance: 10
C34 = 000070: Ceramic capacitor; Partnumber: 000070; Manufacturer: Kemet; ValueFloat: 1E-7; Tolerance (%): 10; Description 2: SM-0402, 10%, 10v
C37 = 000070: Partnumber: 000070; manufacturer: Kemet; manufacturer_pn: C0402C104K8PACTU; ValueFloat: 1E-7; id: 750; inventory_price: 0.0023; reorder_quantity: 70000; x_tolerance: 10
C47 = 001172: Partnumber: 001172; manufacturer: TDK; ValueFloat: 2.2E-5; x_tolerance: 20; x_voltage-rating: 35
C48 = 001073: Partnumber: 001073; manufacturer: Taiyo Yuden; ValueFloat: 1E-7; x_tolerance: 10
C49 C50 = 001284: Partnumber: 001284; manufacturer: Taiyo Yuden; ValueFloat: 2.2E-5; x_tolerance: 10
C54 = 001297: Partnumber: 001297; manufacturer: Kemet; ValueFloat: 1E-11; x_tolerance: 5; x_voltage-rating: 50
C55 = 001277: Partnumber: 001277; manufacturer: Kemet; ValueFloat: 3.3E-9; x_tolerance: 10; x_voltage-rating: 50
C56 = 000480: Partnumber: 000480; manufacturer: Taiyo Yuden; ValueFloat: 1E-6; x_tolerance: 10
D1 D2 = 001433: LED; Manufacturer: Dialight; Manufacturer_PN: 598-8070-107F; partnumber: 001433; Description 2: SM-0603, green; x_lifecycle_status: Production
D3 = 002130: High Conductance, Ultra Fast Diode; Partnumber: 002130; Manufacturer: Micro Commercial Co; Description 2: 100V 350MA SOT23
D4 = 002129: Transient Voltage Suppressor; Manufacturer: Diodes Incorporated; PartNumber: 002129; Manufacturer_PN: SMBJ15CA-13-F; Class I: Discrete; Class II: Diode - Transorb; Description 2: TVS, 600W, 15V, SMB, Bi-Directional
FID1-FID4 = FIDUCIAL: PCB fiducial
J1 = 001335: U.FL surface-mount coaxial connector; Manufacturer: Hirose; Manufacturer_PN: U.FL-R-SMT-1; partnumber: 001335; x_lifecycle_status: Production
J2 = 001193: Partnumber: 001193; manufacturer: Sullins Electronics Corp.
J3 = 002124: Partnumber: 002124; manufacturer: Molex
J4 = 000356: DC power connector - high current; Manufacturer: CUI Inc.; partnumber: 000356; Description 2: 2.1mm / 5.5mm
J5 = 001950: Partnumber: 001950; manufacturer: Molex
L14 = 002116: Partnumber: 002116; manufacturer: Murata; ValueFloat: 3.3E-6; x_tolerance: 30
LABEL1 = 000605: Barcode serial number labels for USB devices; Manufacturer: Techiant; partnumber: 000605; Description 2: 4-digit, all four, alphanumeric, case insensitive; x_lifecycle_status: Production
MB1-MB6 = MouseBite
MC1 = 002562: 0.635mm hi-speed, high-density socket (female); Manufacturer: Samtec; partnumber: 002562; Description 2: 100-pin, 2.5mm wide, 28 Gbps NRZ
MC2 MC3 = 002561: 0.635mm hi-speed, high-density socket (female); Manufacturer: Samtec; partnumber: 002561; Description 2: 80-pin, 2.5mm wide, 28 Gbps NRZ
MC4-MC6 = 000583: Partnumber: 000583; manufacturer: Molex; id: 9990; inventory_price: 1.03
MC7-MC9 = 001334: PartNumber: 001334; manufacturer: 3M; manufacturer_pn: 951120-8622-AR; id: 98023; inventory_price: 0.924
MH1-MH4 = MTG: Mounting hole
PCB1 = 002590: PCB for BRK8305; Partnumber: 002590; Manufacturer: Generic PCB Manufacturer
Q2 = 002018: Partnumber: 002018; manufacturer: Vishay
R1 = 001070: Thick-film resistor; Partnumber: 001070; Manufacturer: Vishay; ValueFloat: 100000; Tolerance (%): 1; Description 2: SM-0402, 1%, 1/16W
R3 R4 = 001162: Thick-film resistor; Manufacturer: Vishay; partnumber: 001162; Description 2: SM-0402, 1%, 1/16W; ValueFloat: 2000; Tolerance (%): 1
R5 R6 = 000411: Zero-ohm resistor; Manufacturer: Vishay; partnumber: 000411; Description 2: SM-0603, 1/10W, 20 mOhm max, 2.0 A max
R19 R34-R36 = 000411: Zero-ohm resistor; Partnumber: 000411; Manufacturer: Vishay; Description 2: SM-0603, 1/10W, 20 mOhm max, 2.0 A max
R75 R79 = 001521: Partnumber: 001521; manufacturer: Vishay; ValueFloat: 10000; x_tolerance: 1
R76 = 000755: Partnumber: 000755; manufacturer: Vishay; x_tolerance: 1
R77 = 002123: Partnumber: 002123; manufacturer: Vishay; ValueFloat: 73200; x_tolerance: 1
R78 = 002121: Partnumber: 002121; manufacturer: Vishay; ValueFloat: 22100; x_tolerance: 1
S1 = SW-PB: Pushbutton; Manufacturer: Generic Components
TP1 TP2 TP17 TP27-TP29 = TP-PTH-25/45: Test point, plated through-hole, 25/45mil
TP3 TP4 TP6 TP8 TP18 TP22-TP26 = TP-PTH-65/100: Test point, plated through-hole, 65/100mil; partnumber: ALIGNI_IGNORE
TP19 TP32 = TESTPOINT-SMD40: Test point, surface-mount, 40mil
TP30 TP31 = TESTPOINT-SMD20: Test point, surface-mount, 20mil; partnumber: ALIGNI_IGNORE
U1 = 000728: 1.25V Voltage Reference; Manufacturer: Texas Instruments; partnumber: 000728; Description 2: 50ppm/C, 50uA
U3 = 002434: Partnumber: 002434; manufacturer: SiTime
U8 = 002537: Partnumber: 002537; Manufacturer: ON Semiconductor; Description 2: 600Mbps, 3.3V, SOT23-5
U10 = 002118: Step-down converter, 4.5 A, 7-18V input, 0.76-5.5V output, 4x4 mm; Partnumber: 002118; Manufacturer: Texas Instruments

## Sheet PCIE.SchDoc: PCIE
size C; Author: Ray Anderson; Organization: Opal Kelly; Address1: 13500 SW 72nd Ave, STE 100; Address2: Portland, OR 97223; Address3: 217.391.3724; Address4: http://www.opalkelly.com; DocumentNumber: 2; Revision: 1; SheetNumber: 2; SheetTotal: 3
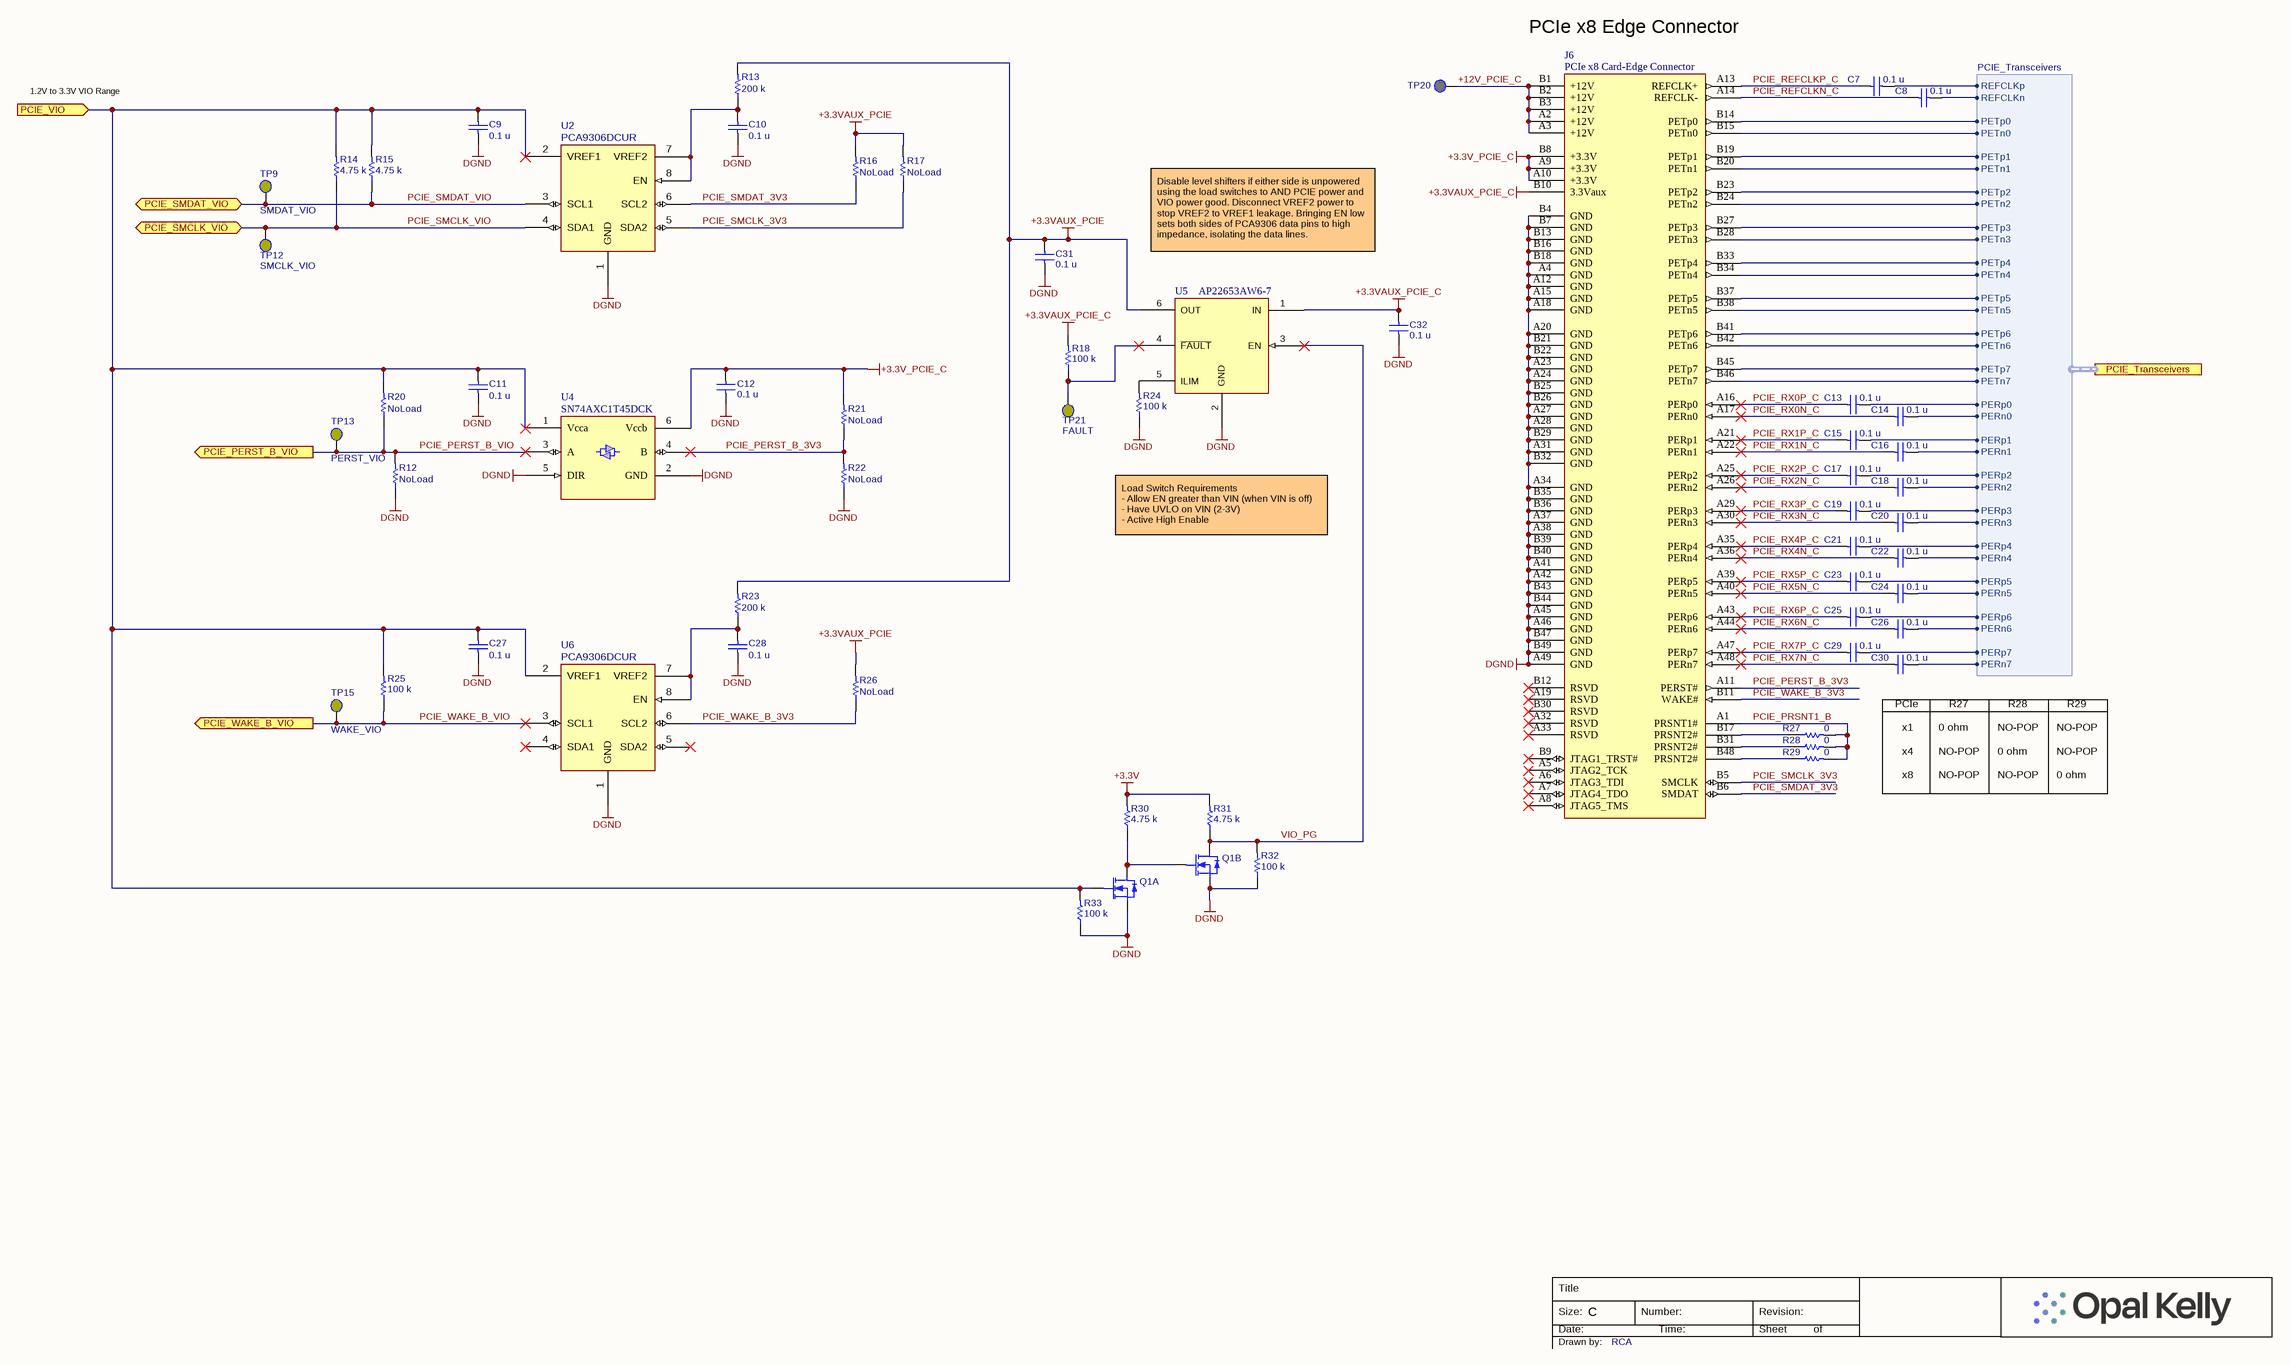
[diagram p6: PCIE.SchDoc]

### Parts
C7  value 0.1 u  [CAPC1005X06A]  (hidden comment: C0402C104K8PACTU)
C8  value 0.1 u  [CAPC1005X06A]  (hidden comment: C0402C104K8PACTU)
C9  value 0.1 u  [CAPC1005X06A]  (hidden comment: C0402C104K8PACTU)
C10  value 0.1 u  [CAPC1005X06A]  (hidden comment: C0402C104K8PACTU)
C11  value 0.1 u  [CAPC1005X06A]  (hidden comment: C0402C104K8PACTU)
C12  value 0.1 u  [CAPC1005X06A]  (hidden comment: C0402C104K8PACTU)
C13  value 0.1 u  [CAPC1005X06A]  (hidden comment: C0402C104K8PACTU)
C14  value 0.1 u  [CAPC1005X06A]  (hidden comment: C0402C104K8PACTU)
C15  value 0.1 u  [CAPC1005X06A]  (hidden comment: C0402C104K8PACTU)
C16  value 0.1 u  [CAPC1005X06A]  (hidden comment: C0402C104K8PACTU)
C17  value 0.1 u  [CAPC1005X06A]  (hidden comment: C0402C104K8PACTU)
C18  value 0.1 u  [CAPC1005X06A]  (hidden comment: C0402C104K8PACTU)
C19  value 0.1 u  [CAPC1005X06A]  (hidden comment: C0402C104K8PACTU)
C20  value 0.1 u  [CAPC1005X06A]  (hidden comment: C0402C104K8PACTU)
C21  value 0.1 u  [CAPC1005X06A]  (hidden comment: C0402C104K8PACTU)
C22  value 0.1 u  [CAPC1005X06A]  (hidden comment: C0402C104K8PACTU)
C23  value 0.1 u  [CAPC1005X06A]  (hidden comment: C0402C104K8PACTU)
C24  value 0.1 u  [CAPC1005X06A]  (hidden comment: C0402C104K8PACTU)
C25  value 0.1 u  [CAPC1005X06A]  (hidden comment: C0402C104K8PACTU)
C26  value 0.1 u  [CAPC1005X06A]  (hidden comment: C0402C104K8PACTU)
C27  value 0.1 u  [CAPC1005X06A]  (hidden comment: C0402C104K8PACTU)
C28  value 0.1 u  [CAPC1005X06A]  (hidden comment: C0402C104K8PACTU)
C29  value 0.1 u  [CAPC1005X06A]  (hidden comment: C0402C104K8PACTU)
C30  value 0.1 u  [CAPC1005X06A]  (hidden comment: C0402C104K8PACTU)
C31  value 0.1 u  [CAPC1005X06A]  (hidden comment: C0402C104K8PACTU)
C32  value 0.1 u  [CAPC1005X06A]  (hidden comment: C0402C104K8PACTU)
J6  PCIe x8 Card-Edge Connector  [PCIEx8-FULL-HEIGHT]
Q1  SI1922EDH-T1-GE3  [SOT363-6N]  (value not drawn)  (parts A,B of 2)
R12  NoLoad  [RESC1005X06A]
R13  value 200 k  [RESC1005X06A]  (hidden comment: CRCW0402200KFKED)
R14  value 4.75 k  [RESC1005X06A]  (hidden comment: CRCW04024K75FKED)
R15  value 4.75 k  [RESC1005X06A]  (hidden comment: CRCW04024K75FKED)
R16  NoLoad  [RESC1005X06A]
R17  NoLoad  [RESC1005X06A]
R18  value 100 k  [RESC1005X06A]  (hidden comment: CRCW0402100KFKED)
R20  NoLoad  [RESC1005X06A]
R21  NoLoad  [RESC1005X06A]
R22  NoLoad  [RESC1005X06A]
R23  value 200 k  [RESC1005X06A]  (hidden comment: CRCW0402200KFKED)
R24  value 100 k  [RESC1005X06A]  (hidden comment: CRCW0402100KFKED)
R25  value 100 k  [RESC1005X06A]  (hidden comment: CRCW0402100KFKED)
R26  NoLoad  [RESC1005X06A]
R27  value 0  [RESC1005X06A]  (hidden comment: CRCW04020000Z0ED)
R28  value 0  [RESC1005X06A]  (hidden comment: CRCW04020000Z0ED)
R29  value 0  [RESC1005X06A]  (hidden comment: CRCW04020000Z0ED)
R30  value 4.75 k  [RESC1005X06A]  (hidden comment: CRCW04024K75FKED)
R31  value 4.75 k  [RESC1005X06A]  (hidden comment: CRCW04024K75FKED)
R32  value 100 k  [RESC1005X06A]  (hidden comment: CRCW0402100KFKED)
R33  value 100 k  [RESC1005X06A]  (hidden comment: CRCW0402100KFKED)
TP9  SMDAT_VIO  [TP-SMD40]
TP12  SMCLK_VIO  [TP-SMD40]
TP13  PERST_VIO  [TP-SMD40]
TP15  WAKE_VIO  [TP-SMD40]
TP20  +12V_PCIE_C  [TP-PTH-65/100]  (value not drawn)
TP21  FAULT  [TP-SMD40]
U2  PCA9306DCUR  [PCA9306DCU]
U4  SN74AXC1T45DCK  [DCK-R-PDSO-G6]
U5  AP22653AW6-7  [AP2265XW6]
U6  PCA9306DCUR  [PCA9306DCU]

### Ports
PCIE_PERST_B_VIO (out), PCIE_SMCLK_VIO (bidir), PCIE_SMDAT_VIO (bidir), PCIE_Transceivers (harness PCIE_Transceivers), PCIE_VIO (in), PCIE_WAKE_B_VIO (out)

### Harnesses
PCIE_Transceivers: PETn3, PETp3, PERn3, PERp3, PETn2, PETp2, PERn2, PERp2, PETn1, PETp1, PERn1, PERp1, PETn0, PETp0, PERn0, PERp0, PETn4, PETp4, PERn4, PERp4, PETn5, PETp5, PERn5, PERp5, PETn6, PETp6, PERn6, PERp6, PETn7, PETp7, PERn7, PERp7, REFCLKn, REFCLKp

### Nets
+3.3V: R30.2 R31.2
+3.3V_PCIE_C: C12.2 J6.A9(+3.3V) J6.A10(+3.3V) J6.B8(+3.3V) R21.2 U4.6(Vccb)
+3.3VAUX_PCIE: C31.2 R13.2 R16.2 R17.2 R23.2 R26.2 U5.6(OUT)
+3.3VAUX_PCIE_C: C32.2 J6.B10(3.3Vaux) R18.2 U5.1(IN)
DGND: C9.1 C10.1 C11.1 C12.1 C27.1 C28.1 C31.1 C32.1 J6.A4(GND) J6.A12(GND) J6.A15(GND) J6.A18(GND) J6.A20(GND) J6.A23(GND) J6.A24(GND) J6.A27(GND) J6.A28(GND) J6.A31(GND) J6.A34(GND) J6.A37(GND) J6.A38(GND) J6.A41(GND) J6.A42(GND) J6.A45(GND) J6.A46(GND) J6.A49(GND) J6.B4(GND) J6.B7(GND) J6.B13(GND) J6.B16(GND) J6.B18(GND) J6.B21(GND) J6.B22(GND) J6.B25(GND) J6.B26(GND) J6.B29(GND) J6.B32(GND) J6.B35(GND) J6.B36(GND) J6.B39(GND) J6.B40(GND) J6.B43(GND) J6.B44(GND) J6.B47(GND) J6.B49(GND) Q1.1(S1) Q1.4(S2) R12.1 R22.1 R24.1 R32.1 R33.1 U2.1(GND) U4.2(GND) U4.5(DIR) U5.2(GND) U6.1(GND)
VCCO_85: C9.2 C11.2 C27.2 Q1.2(G1) R14.2 R15.2 R20.2 R25.2 R33.2 U2.2(VREF1) U4.1(Vcca) U6.2(VREF1) ; port PCIE_VIO
+12V_PCIE_C: J6.A2(+12V) J6.A3(+12V) J6.B1(+12V) J6.B2(+12V) J6.B3(+12V) TP20.1(PIN)
MGT_REFCLK0N_225_C: C8.2 ; port PCIE_Transceivers.REFCLKn
MGT_REFCLK0P_225_C: C7.2 ; port PCIE_Transceivers.REFCLKp
MGT_RXN0_224: J6.B46(PETn7) ; port PCIE_Transceivers.PETn7
MGT_RXN0_225: J6.B28(PETn3) ; port PCIE_Transceivers.PETn3
MGT_RXN1_224: J6.B42(PETn6) ; port PCIE_Transceivers.PETn6
MGT_RXN1_225: J6.B24(PETn2) ; port PCIE_Transceivers.PETn2
MGT_RXN2_224: J6.B38(PETn5) ; port PCIE_Transceivers.PETn5
MGT_RXN2_225: J6.B20(PETn1) ; port PCIE_Transceivers.PETn1
MGT_RXN3_224: J6.B34(PETn4) ; port PCIE_Transceivers.PETn4
MGT_RXN3_225: J6.B15(PETn0) ; port PCIE_Transceivers.PETn0
MGT_RXP0_224: J6.B45(PETp7) ; port PCIE_Transceivers.PETp7
MGT_RXP0_225: J6.B27(PETp3) ; port PCIE_Transceivers.PETp3
MGT_RXP1_224: J6.B41(PETp6) ; port PCIE_Transceivers.PETp6
MGT_RXP1_225: J6.B23(PETp2) ; port PCIE_Transceivers.PETp2
MGT_RXP2_224: J6.B37(PETp5) ; port PCIE_Transceivers.PETp5
MGT_RXP2_225: J6.B19(PETp1) ; port PCIE_Transceivers.PETp1
MGT_RXP3_224: J6.B33(PETp4) ; port PCIE_Transceivers.PETp4
MGT_RXP3_225: J6.B14(PETp0) ; port PCIE_Transceivers.PETp0
MGT_TXN0_224: C30.2 ; port PCIE_Transceivers.PERn7
MGT_TXN0_225: C20.2 ; port PCIE_Transceivers.PERn3
MGT_TXN1_224: C26.2 ; port PCIE_Transceivers.PERn6
MGT_TXN1_225: C18.2 ; port PCIE_Transceivers.PERn2
MGT_TXN2_224: C24.2 ; port PCIE_Transceivers.PERn5
MGT_TXN2_225: C16.2 ; port PCIE_Transceivers.PERn1
MGT_TXN3_224: C22.2 ; port PCIE_Transceivers.PERn4
MGT_TXN3_225: C14.2 ; port PCIE_Transceivers.PERn0
MGT_TXP0_224: C29.2 ; port PCIE_Transceivers.PERp7
MGT_TXP0_225: C19.2 ; port PCIE_Transceivers.PERp3
MGT_TXP1_224: C25.2 ; port PCIE_Transceivers.PERp6
MGT_TXP1_225: C17.2 ; port PCIE_Transceivers.PERp2
MGT_TXP2_224: C23.2 ; port PCIE_Transceivers.PERp5
MGT_TXP2_225: C15.2 ; port PCIE_Transceivers.PERp1
MGT_TXP3_224: C21.2 ; port PCIE_Transceivers.PERp4
MGT_TXP3_225: C13.2 ; port PCIE_Transceivers.PERp0
PCIE_PERST_B_3V3: J6.A11(PERST#) R21.1 R22.2 U4.4(B)
PCIE_PERST_B_VIO: R12.2 R20.1 TP13.1(PIN) U4.3(A) ; port PCIE_PERST_B_VIO
PCIE_PRSNT1_B: J6.A1(PRSNT1#) R27.2 R28.2 R29.2
PCIE_REFCLKN_C: C8.1 J6.A14(REFCLK-)
PCIE_REFCLKP_C: C7.1 J6.A13(REFCLK+)
PCIE_RX0N_C: C14.1 J6.A17(PERn0)
PCIE_RX0P_C: C13.1 J6.A16(PERp0)
PCIE_RX1N_C: C16.1 J6.A22(PERn1)
PCIE_RX1P_C: C15.1 J6.A21(PERp1)
PCIE_RX2N_C: C18.1 J6.A26(PERn2)
PCIE_RX2P_C: C17.1 J6.A25(PERp2)
PCIE_RX3N_C: C20.1 J6.A30(PERn3)
PCIE_RX3P_C: C19.1 J6.A29(PERp3)
PCIE_RX4N_C: C22.1 J6.A36(PERn4)
PCIE_RX4P_C: C21.1 J6.A35(PERp4)
PCIE_RX5N_C: C24.1 J6.A40(PERn5)
PCIE_RX5P_C: C23.1 J6.A39(PERp5)
PCIE_RX6N_C: C26.1 J6.A44(PERn6)
PCIE_RX6P_C: C25.1 J6.A43(PERp6)
PCIE_RX7N_C: C30.1 J6.A48(PERn7)
PCIE_RX7P_C: C29.1 J6.A47(PERp7)
PCIE_SMCLK_3V3: J6.B5(SMCLK) R17.1 U2.5(SDA2)
PCIE_SMCLK_VIO: R14.1 TP12.1(PIN) U2.4(SDA1) ; port PCIE_SMCLK_VIO
PCIE_SMDAT_3V3: J6.B6(SMDAT) R16.1 U2.6(SCL2)
PCIE_SMDAT_VIO: R15.1 TP9.1(PIN) U2.3(SCL1) ; port PCIE_SMDAT_VIO
PCIE_WAKE_B_3V3: J6.B11(WAKE#) R26.1 U6.6(SCL2)
PCIE_WAKE_B_VIO: R25.1 TP15.1(PIN) U6.3(SCL1) ; port PCIE_WAKE_B_VIO
VIO_PG: Q1.3(D2) R31.1 R32.2 U5.3(EN)
NetC10_2: C10.2 R13.1 U2.7(VREF2) U2.8(EN)
NetC28_2: C28.2 R23.1 U6.7(VREF2) U6.8(EN)
NetJ6_B17: J6.B17(PRSNT2#) R27.1
NetJ6_B31: J6.B31(PRSNT2#) R28.1
NetJ6_B48: J6.B48(PRSNT2#) R29.1
NetQ1_5: Q1.5(G2) Q1.6(D1) R30.1
NetR18_1: R18.1 TP21.1(PIN) U5.4(~{FAULT})
NetR24_2: R24.2 U5.5(ILIM)

Not connected (* = marked no-connect by the designer): J6 A5(JTAG2_TCK)* A6(JTAG3_TDI)* A7(JTAG4_TDO)* A8(JTAG5_TMS)* A19(RSVD)* A32(RSVD)* A33(RSVD)* B9(JTAG1_TRST#)* B12(RSVD)* B30(RSVD)*; U6 4(SDA1)* 5(SDA2)*

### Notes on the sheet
- PCIe x8 Edge Connector
- 1.2V to 3.3V VIO Range
- Disable level shifters if either side is unpowered using the load switches to AND PCIE power and VIO power good. Disconnect VREF2 power to stop VREF2 to VREF1 leakage. Bringing EN low sets both sides of PCA9306 data pins to high impedance, isolating the data lines.
- Load Switch Requirements
  - Allow EN greater than VIN (when VIN is off)
  - Have UVLO on VIN (2-3V)
  - Active High Enable
- (near C30) PCIe
- x1
- x4
- 0 ohm
- NO-POP
- R27
- R28
- R29
- x8
- Title
- Size:
- Date:
- Drawn by:
- C
- RCA
- Number:
- Time:
- Revision:
- Sheet
- of

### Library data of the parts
C7-C32 = 001073: Partnumber: 000070; manufacturer: Kemet; ValueFloat: 1E-7; x_tolerance: 10
J6 = PCIEX8
Q1 = 002018: Partnumber: 002018; manufacturer: Vishay
R12 R16 R17 R20-R22 R26 = Resistor-NoLoad: Resistor, NoLoad; partnumber: ALIGNI_IGNORE
R13 R23 = 000964: Partnumber: 000964; manufacturer: Vishay; ValueFloat: 200000; x_tolerance: 1
R14 R15 R30 R31 = 001008: Partnumber: 001008; manufacturer: Vishay; ValueFloat: 4750; x_tolerance: 1
R18 R24 R25 R32 R33 = 001070: as R1 on sheet BRK8305
R27-R29 = 000755: as R76 on sheet BRK8305
TP9 TP12 TP13 TP15 TP21 = TESTPOINT-SMD40: Test point, surface-mount, 40mil
TP20 = TP-PTH-65/100: Test point, plated through-hole, 65/100mil
U2 U6 = 001474: Partnumber: 001474; manufacturer: Texas Instruments
U4 = 002140: Level Translator, 0.65V - 3.6V, Direction Control; Partnumber: 002140; Manufacturer: Texas Instruments; Description 2: Single Bit, Dual Supplies
U5 = 002224: Load Switch with Adjustable Current Limit, Latching; Partnumber: 002224; Manufacturer: Diodes Incorporated; Description 2: 3V - 5.5V, 125mA to 2665mA Limit, Fault Out

## Sheet QSFP.SchDoc: QSFP
size C; Author: RCA; Organization: Opal Kelly; Address1: 13500 SW 72nd Ave STE 100; Address2: Portland, OR 97223; Address3: 217.391.3724; Address4: http://www.opalkelly.com; DocumentNumber: 3; Revision: 1; SheetNumber: 3; SheetTotal: 3
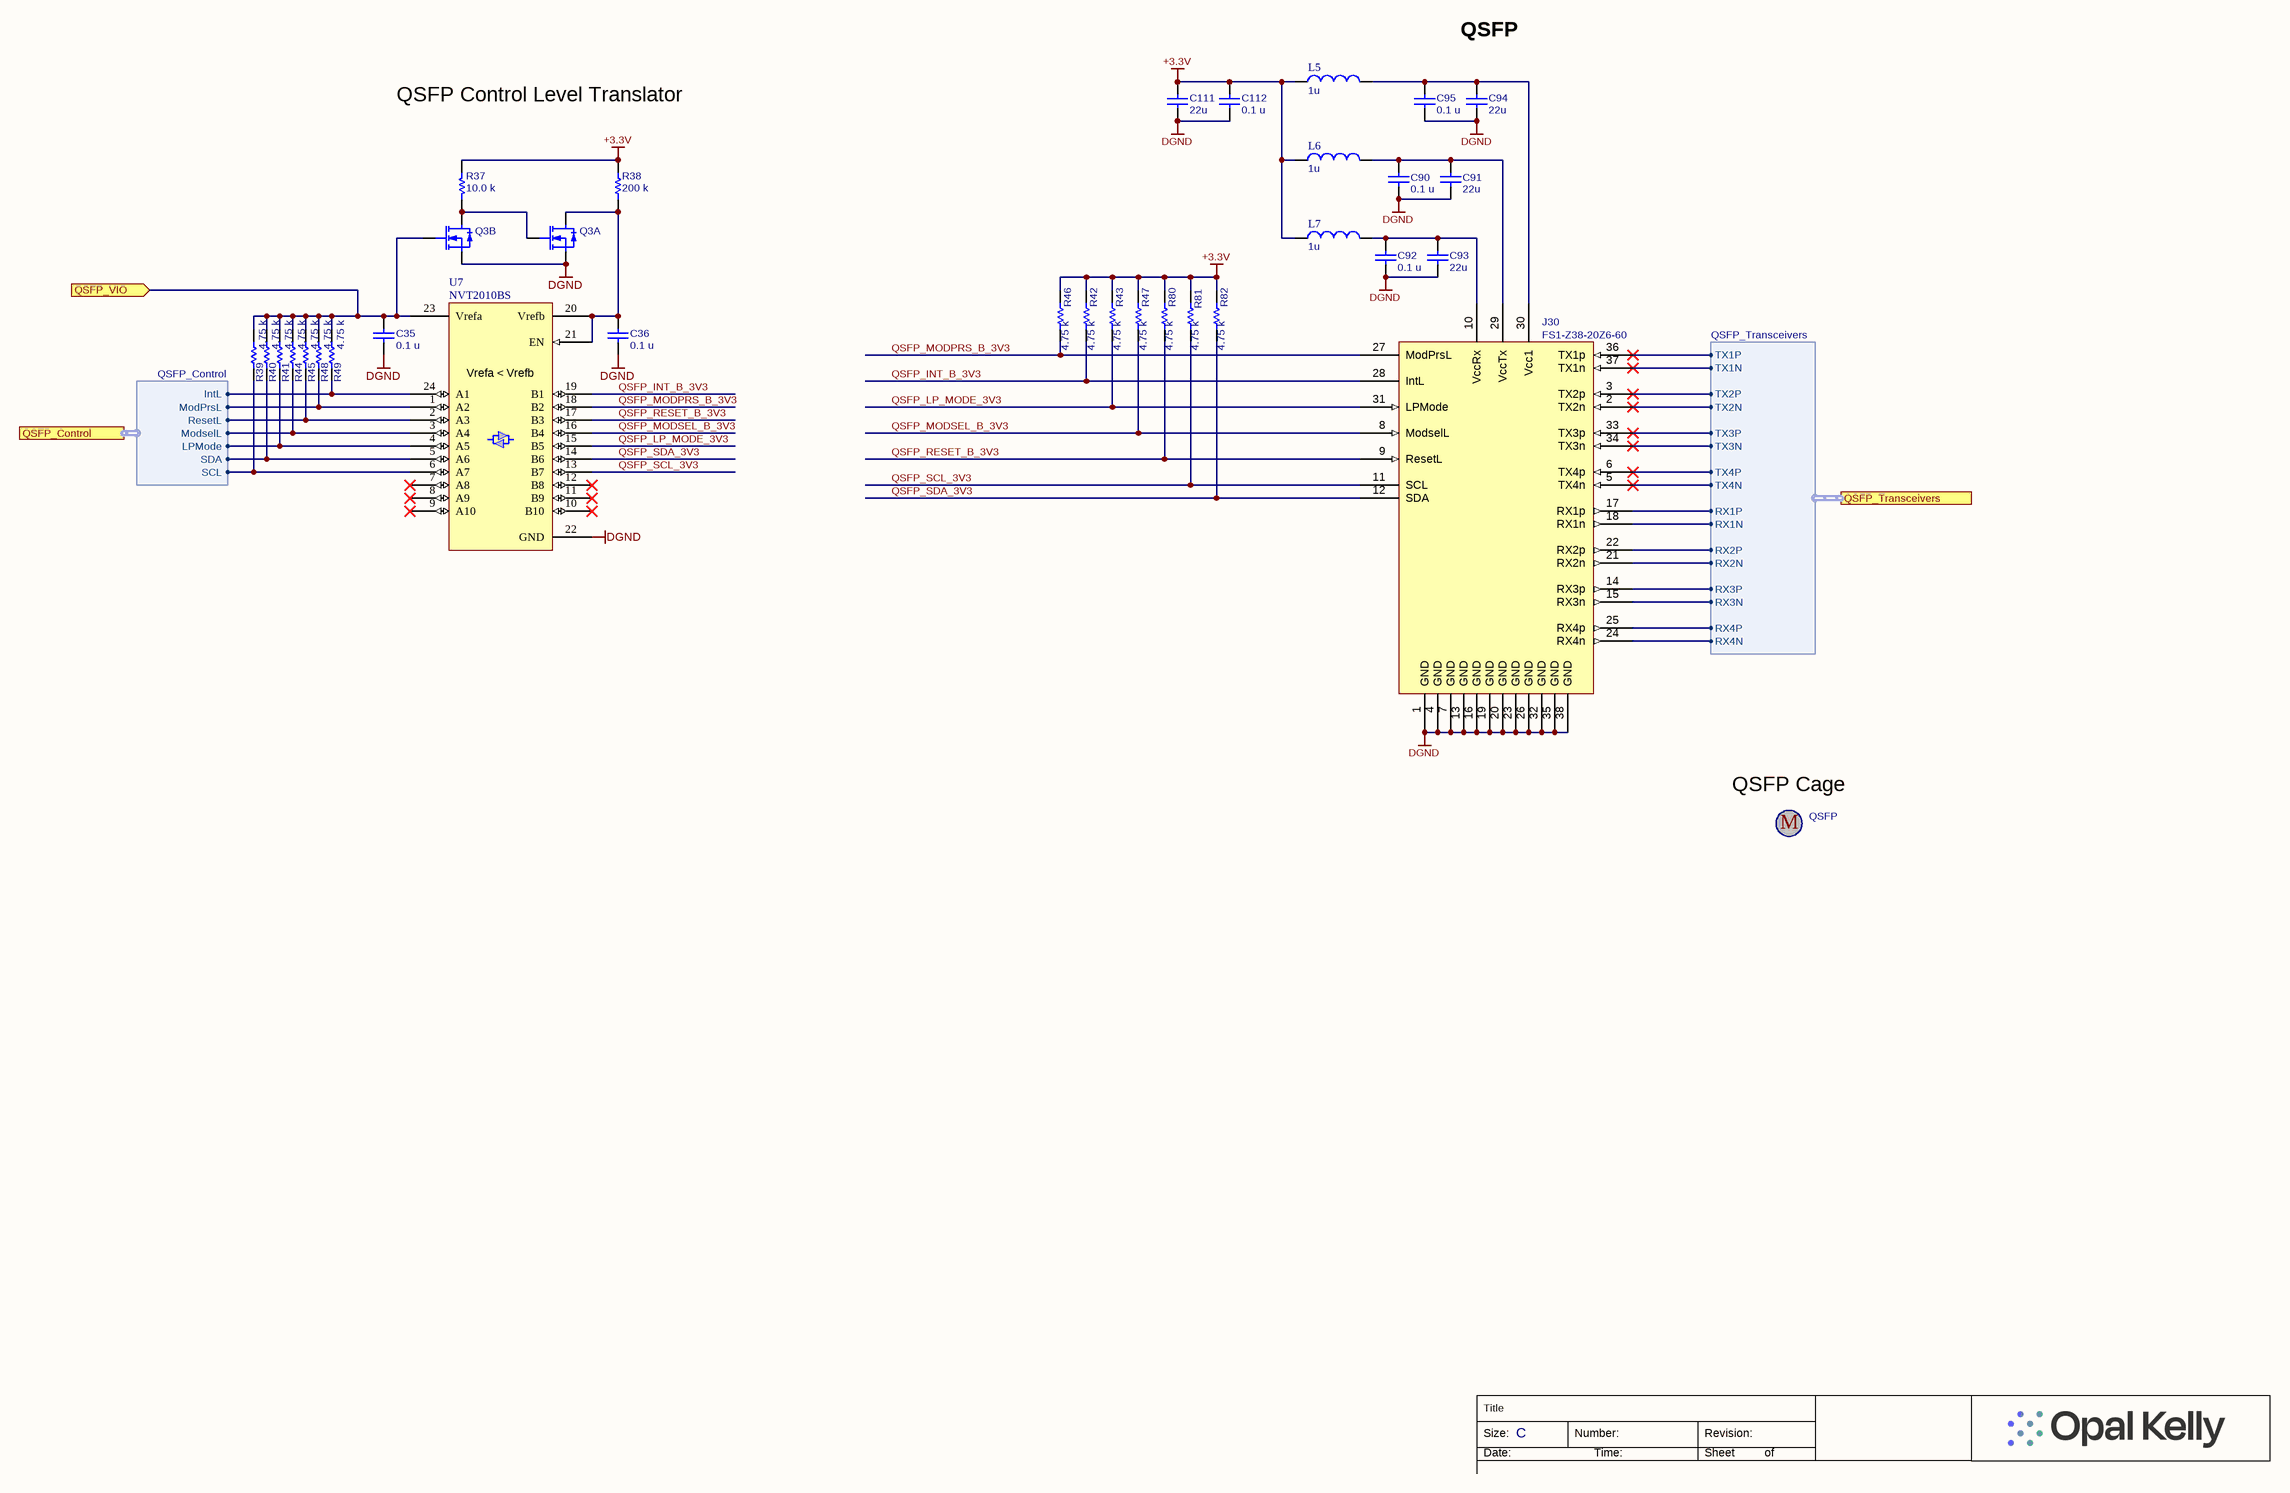
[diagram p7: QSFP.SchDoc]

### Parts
C35  value 0.1 u  [CAPC1005X06A]  (hidden comment: SM-0402, 10%, 10v)
C36  value 0.1 u  [CAPC1005X06A]  (hidden comment: SM-0402, 10%, 10v)
C90  value 0.1 u  [CAPC1005X06A]  (hidden comment: SM-0402, 10%, 10v)
C91  value 22u  [CAPC3216N]  (hidden comment: SM-1206, 10%, 10v, X7R)
C92  value 0.1 u  [CAPC1005X06A]  (hidden comment: SM-0402, 10%, 10v)
C93  value 22u  [CAPC3216N]  (hidden comment: SM-1206, 10%, 10v, X7R)
C94  value 22u  [CAPC3216N]  (hidden comment: SM-1206, 10%, 10v, X7R)
C95  value 0.1 u  [CAPC1005X06A]  (hidden comment: SM-0402, 10%, 10v)
C111  value 22u  [CAPC3216N]  (hidden comment: SM-1206, 10%, 10v, X7R)
C112  value 0.1 u  [CAPC1005X06A]  (hidden comment: SM-0402, 10%, 10v)
J30  FS1-Z38-20Z6-60  [QSFP28_RECEPTACLE_SFF-8679]
L5  value 1u  [CIGT252010]  (hidden comment: CIGT252010LM1R0MNE)
L6  value 1u  [CIGT252010]  (hidden comment: CIGT252010LM1R0MNE)
L7  value 1u  [CIGT252010]  (hidden comment: CIGT252010LM1R0MNE)
Q3  SI1922EDH-T1-GE3  [SOT363-6N]  (value not drawn)  (parts A,B of 2)
QSFP  Pressfit  [QSFP28_SINGLE_CAGE]  (value not drawn)
R37  value 10.0 k  [RESC1005X06A]  (hidden comment: CRCW040210K0FKED)
R38  value 200 k  [RESC1005X06A]  (hidden comment: CRCW0402200KFKED)
R39  value 4.75 k  [RESC1005X06A]  (hidden comment: CRCW04024K75FKED)
R40  value 4.75 k  [RESC1005X06A]  (hidden comment: CRCW04024K75FKED)
R41  value 4.75 k  [RESC1005X06A]  (hidden comment: CRCW04024K75FKED)
R42  value 4.75 k  [RESC1005X06A]  (hidden comment: CRCW04024K75FKED)
R43  value 4.75 k  [RESC1005X06A]  (hidden comment: CRCW04024K75FKED)
R44  value 4.75 k  [RESC1005X06A]  (hidden comment: CRCW04024K75FKED)
R45  value 4.75 k  [RESC1005X06A]  (hidden comment: CRCW04024K75FKED)
R46  value 4.75 k  [RESC1005X06A]  (hidden comment: CRCW04024K75FKED)
R47  value 4.75 k  [RESC1005X06A]  (hidden comment: CRCW04024K75FKED)
R48  value 4.75 k  [RESC1005X06A]  (hidden comment: CRCW04024K75FKED)
R49  value 4.75 k  [RESC1005X06A]  (hidden comment: CRCW04024K75FKED)
R80  value 4.75 k  [RESC1005X06A]  (hidden comment: CRCW04024K75FKED)
R81  value 4.75 k  [RESC1005X06A]  (hidden comment: CRCW04024K75FKED)
R82  value 4.75 k  [RESC1005X06A]  (hidden comment: CRCW04024K75FKED)
U7  NVT2010BS  [QFN-24]

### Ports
QSFP_Control (harness QSFP_Control), QSFP_Transceivers (harness QSFP_Transceivers), QSFP_VIO (in)

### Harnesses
QSFP_Transceivers: TX1P, TX1N, TX2P, TX2N, TX3P, TX3N, TX4P, TX4N, RX1P, RX1N, RX2P, RX2N, RX3P, RX3N, RX4P, RX4N
QSFP_Control: ModPrsL, IntL, LPMode, ModselL, ResetL, SCL, SDA

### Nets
+3.3V: C111.2 C112.2 L5.1 L6.1 L7.1 R37.2 R38.2 R42.2 R43.2 R46.2 R47.2 R80.2 R81.2 R82.2
DGND: C35.1 C36.1 C90.1 C91.1 C92.1 C93.1 C94.1 C95.1 C111.1 C112.1 J30.1(GND) J30.4(GND) J30.7(GND) J30.13(GND) J30.16(GND) J30.19(GND) J30.20(GND) J30.23(GND) J30.26(GND) J30.32(GND) J30.35(GND) J30.38(GND) Q3.1(S1) Q3.4(S2) U7.22(GND)
VCCO_85: C35.2 Q3.5(G2) R39.2 R40.2 R41.2 R44.2 R45.2 R48.2 R49.2 U7.23(Vrefa) ; port QSFP_VIO
MGT_RXN0_226: J30.18(RX1n) ; port QSFP_Transceivers.RX1N
MGT_RXN1_226: J30.21(RX2n) ; port QSFP_Transceivers.RX2N
MGT_RXN2_226: J30.15(RX3n) ; port QSFP_Transceivers.RX3N
MGT_RXN3_226: J30.24(RX4n) ; port QSFP_Transceivers.RX4N
MGT_RXP0_226: J30.17(RX1p) ; port QSFP_Transceivers.RX1P
MGT_RXP1_226: J30.22(RX2p) ; port QSFP_Transceivers.RX2P
MGT_RXP2_226: J30.14(RX3p) ; port QSFP_Transceivers.RX3P
MGT_RXP3_226: J30.25(RX4p) ; port QSFP_Transceivers.RX4P
MGT_TXN0_226: J30.37(TX1n) ; port QSFP_Transceivers.TX1N
MGT_TXN1_226: J30.2(TX2n) ; port QSFP_Transceivers.TX2N
MGT_TXN2_226: J30.34(TX3n) ; port QSFP_Transceivers.TX3N
MGT_TXN3_226: J30.5(TX4n) ; port QSFP_Transceivers.TX4N
MGT_TXP0_226: J30.36(TX1p) ; port QSFP_Transceivers.TX1P
MGT_TXP1_226: J30.3(TX2p) ; port QSFP_Transceivers.TX2P
MGT_TXP2_226: J30.33(TX3p) ; port QSFP_Transceivers.TX3P
MGT_TXP3_226: J30.6(TX4p) ; port QSFP_Transceivers.TX4P
QSFP_INT_B_3V3: J30.28(IntL) R42.1 U7.19(B1)
QSFP_INT_B_VIO: R49.1 U7.24(A1) ; port QSFP_Control.IntL
QSFP_LP_MODE_3V3: J30.31(LPMode) R43.1 U7.15(B5)
QSFP_LP_MODE_VIO: R41.1 U7.4(A5) ; port QSFP_Control.LPMode
QSFP_MODPRS_B_3V3: J30.27(ModPrsL) R46.1 U7.18(B2)
QSFP_MODPRS_B_VIO: R48.1 U7.1(A2) ; port QSFP_Control.ModPrsL
QSFP_MODSEL_B_3V3: J30.8(ModselL) R47.1 U7.16(B4)
QSFP_MODSEL_B_VIO: R44.1 U7.3(A4) ; port QSFP_Control.ModselL
QSFP_RESET_B_3V3: J30.9(ResetL) R80.1 U7.17(B3)
QSFP_RESET_B_VIO: R45.1 U7.2(A3) ; port QSFP_Control.ResetL
QSFP_SCL_3V3: J30.11(SCL) R81.1 U7.13(B7)
QSFP_SCL_VIO: R39.1 U7.6(A7) ; port QSFP_Control.SCL
QSFP_SDA_3V3: J30.12(SDA) R82.1 U7.14(B6)
QSFP_SDA_VIO: R40.1 U7.5(A6) ; port QSFP_Control.SDA
NetC36_2: C36.2 Q3.6(D1) R38.1 U7.20(Vrefb) U7.21(EN)
NetC90_2: C90.2 C91.2 J30.29(VccTx) L6.2
NetC92_2: C92.2 C93.2 J30.10(VccRx) L7.2
NetC94_2: C94.2 C95.2 J30.30(Vcc1) L5.2
NetQ3_2: Q3.2(G1) Q3.3(D2) R37.1

Not connected (* = marked no-connect by the designer): U7 7(A8)* 8(A9)* 9(A10)* 10(B10)* 11(B9)* 12(B8)*

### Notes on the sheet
- QSFP
- QSFP Control Level Translator
- (near QSFP) QSFP Cage
- Title
- Size:
- Date:
- C
- Number:
- Time:
- Revision:
- Sheet
- of

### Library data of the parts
C35 C36 C90 C92 C95 C112 = 000070: as C37 on sheet BRK8305
C91 C93 C94 C111 = 001284: Partnumber: 001284; manufacturer: Taiyo Yuden; manufacturer_pn: LMK316AB7226KL-TR; ValueFloat: 2.2E-5; id: 60625; inventory_price: 0.14; reorder_quantity: 4000; x_tolerance: 10
J30 = 001782: Partnumber: 001782; manufacturer: Amphenol; id: 254667; inventory_price: 4
L5-L7 = 002331: Thin Film, 1uH, 3.1A, 50mOhm, Unshielded; Partnumber: 002331; Manufacturer: Samsung Electro-Mechanics; ValueFloat: 1E-6; Tolerance (%): 20; Description 2: 1008 (2520 Metric)
Q3 = 002018: Partnumber: 002018; manufacturer: Vishay
QSFP = 001781: Partnumber: 001781; manufacturer: Amphenol; manufacturer_pn: U95-T111-1001; id: 254666; inventory_price: 3.5
R37 = 001521: Thick-film resistor; Manufacturer: Vishay; Partnumber: 001521; Description 2: SM-0402, 1%, 1/16W; ValueFloat: 10000; Tolerance (%): 1
R38 = 000964: Thick-film resistor; Partnumber: 000964; Manufacturer: Vishay; ValueFloat: 200000; Tolerance (%): 1; Description 2: SM-0402, 1%, 1/16W
R39-R49 R80-R82 = 001008: as R14 on sheet PCIE
U7 = 002527: Partnumber: 002527; Manufacturer: NXP

## Sheet JTAG.SchDoc: JTAG
size C; Author: Casey Smith; Organization: Opal Kelly; Address1: 13500 SW 72nd Ave STE 100; Address2: Portland, OR 97223; Address3: 217.391.3724; Address4: http://www.opalkelly.com; DocumentNumber: 8; Revision: 1; SheetNumber: 8; SheetTotal: 8
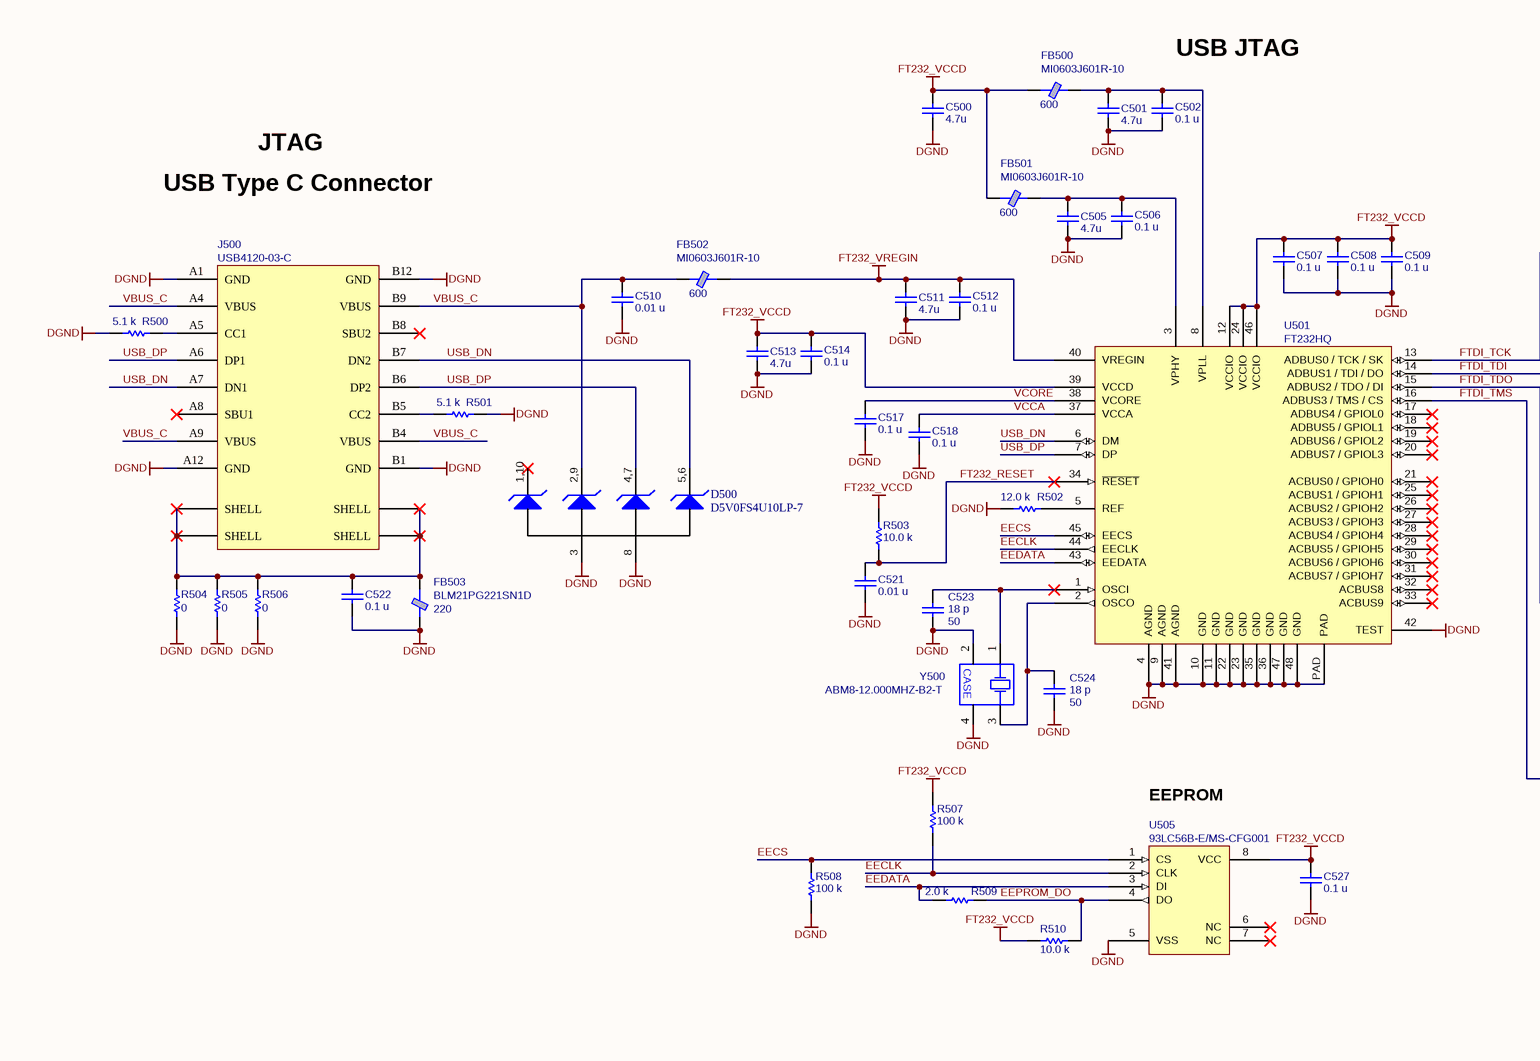
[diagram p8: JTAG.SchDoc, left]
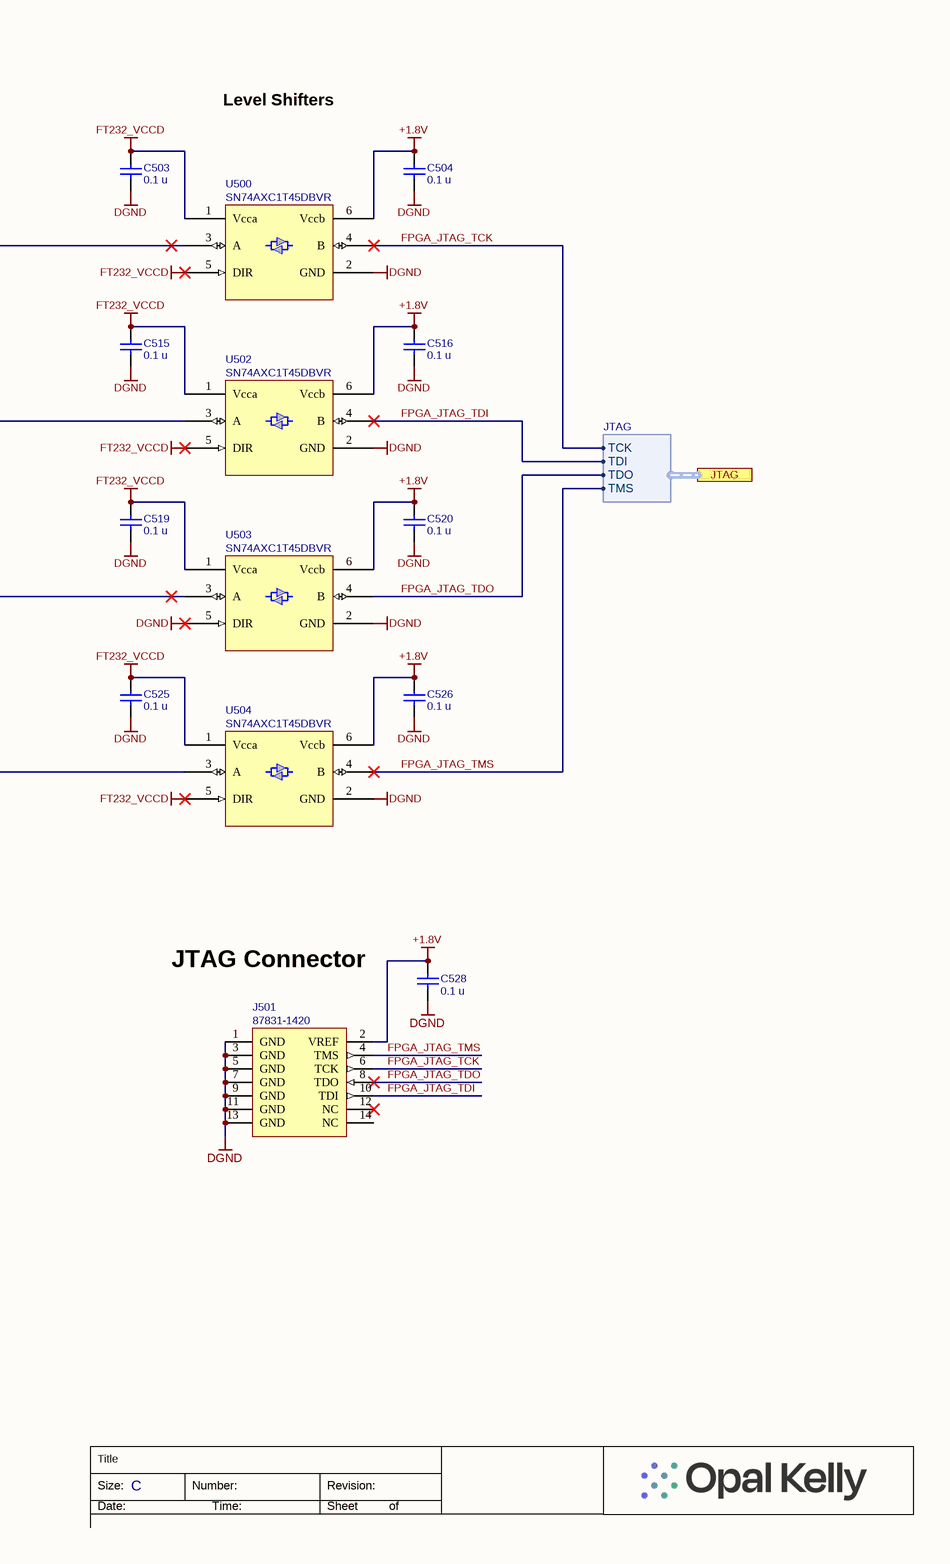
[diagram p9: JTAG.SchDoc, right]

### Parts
C500  value 4.7u  [CAPC1005X06A]  (hidden comment: JMK105BBJ475MV-F)
C501  value 4.7u  [CAPC1005X06A]  (hidden comment: JMK105BBJ475MV-F)
C502  value 0.1 u  [CAPC1005X06A]  (hidden comment: C0402C104K8PACTU)
C503  value 0.1 u  [CAPC1005X06A]  (hidden comment: C0402C104K8PACTU)
C504  value 0.1 u  [CAPC1005X06A]  (hidden comment: C0402C104K8PACTU)
C505  value 4.7u  [CAPC1005X06A]  (hidden comment: JMK105BBJ475MV-F)
C506  value 0.1 u  [CAPC1005X06A]  (hidden comment: C0402C104K8PACTU)
C507  value 0.1 u  [CAPC1005X06A]  (hidden comment: C0402C104K8PACTU)
C508  value 0.1 u  [CAPC1005X06A]  (hidden comment: C0402C104K8PACTU)
C509  value 0.1 u  [CAPC1005X06A]  (hidden comment: C0402C104K8PACTU)
C510  value 0.01 u  [CAPC1005X06A]  (hidden comment: C0402C103K4RACTU)
C511  value 4.7u  [CAPC1005X06A]  (hidden comment: JMK105BBJ475MV-F)
C512  value 0.1 u  [CAPC1005X06A]  (hidden comment: C0402C104K8PACTU)
C513  value 4.7u  [CAPC1005X06A]  (hidden comment: JMK105BBJ475MV-F)
C514  value 0.1 u  [CAPC1005X06A]  (hidden comment: C0402C104K8PACTU)
C515  value 0.1 u  [CAPC1005X06A]  (hidden comment: C0402C104K8PACTU)
C516  value 0.1 u  [CAPC1005X06A]  (hidden comment: C0402C104K8PACTU)
C517  value 0.1 u  [CAPC1005X06A]  (hidden comment: C0402C104K8PACTU)
C518  value 0.1 u  [CAPC1005X06A]  (hidden comment: C0402C104K8PACTU)
C519  value 0.1 u  [CAPC1005X06A]  (hidden comment: C0402C104K8PACTU)
C520  value 0.1 u  [CAPC1005X06A]  (hidden comment: C0402C104K8PACTU)
C521  value 0.01 u  [CAPC1005X06A]  (hidden comment: C0402C103K4RACTU)
C522  value 0.1 u  [CAPC1005X06A]  (hidden comment: SM-0402, 10%, 10v)
C523  value 18 p  Voltage: 50  [CAPC1005X06A]  (hidden comment: C0402C180J5GACTU)
C524  value 18 p  Voltage: 50  [CAPC1005X06A]  (hidden comment: C0402C180J5GACTU)
C525  value 0.1 u  [CAPC1005X06A]  (hidden comment: C0402C104K8PACTU)
C526  value 0.1 u  [CAPC1005X06A]  (hidden comment: C0402C104K8PACTU)
C527  value 0.1 u  [CAPC1005X06A]  (hidden comment: C0402C104K8PACTU)
C528  value 0.1 u  [CAPC1005X06A]  (hidden comment: SM-0402, 10%, 10v)
D500  D5V0FS4U10LP-7  [D5V0FS4U10LP]
FB500  MI0603J601R-10  value 600  [INDC1608X06N]
FB501  MI0603J601R-10  value 600  [INDC1608X06N]
FB502  MI0603J601R-10  value 600  [INDC1608X06N]
FB503  BLM21PG221SN1D  value 220  [RESC2012N]
J500  USB4120-03-C  [USB4120-03-C]
J501  87831-1420  [XILINX-JTAG]
R500  value 5.1 k  [RESC1005X06A]  (hidden comment: CRCW04025K10FKEDC)
R501  value 5.1 k  [RESC1005X06A]  (hidden comment: CRCW04025K10FKEDC)
R502  value 12.0 k  [RESC1005X06A]  (hidden comment: CRCW040212K0FKED)
R503  value 10.0 k  [RESC1005X06A]  (hidden comment: CRCW040210K0FKED)
R504  value 0  [RESC1005X06A]  (hidden comment: CRCW04020000Z0ED)
R505  value 0  [RESC1005X06A]  (hidden comment: CRCW04020000Z0ED)
R506  value 0  [RESC1005X06A]  (hidden comment: CRCW04020000Z0ED)
R507  value 100 k  [RESC1005X06A]  (hidden comment: CRCW0402100KFKED)
R508  value 100 k  [RESC1005X06A]  (hidden comment: CRCW0402100KFKED)
R509  value 2.0 k  [RESC1005X06A]  (hidden comment: CRCW04022K00FKED)
R510  value 10.0 k  [RESC1005X06A]  (hidden comment: CRCW040210K0FKED)
U500  SN74AXC1T45DBVR  [SOT23-6]
U501  FT232HQ  [FT232HQ]
U502  SN74AXC1T45DBVR  [SOT23-6]
U503  SN74AXC1T45DBVR  [SOT23-6]
U504  SN74AXC1T45DBVR  [SOT23-6]
U505  93LC56B-E/MS-CFG001  [MSOP-MS8_N]
Y500  ABM8-12.000MHZ-B2-T  [ABM8]

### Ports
JTAG (harness JTAG)

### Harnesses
JTAG: TDI, TDO, TCK, TMS

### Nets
+1.8V: C504.2 C516.2 C520.2 C526.2 C528.2 J501.2(VREF) U500.6(Vccb) U502.6(Vccb) U503.6(Vccb) U504.6(Vccb)
DGND: C500.1 C501.1 C502.1 C503.1 C504.1 C505.1 C506.1 C507.1 C508.1 C509.1 C510.1 C511.1 C512.1 C513.1 C514.1 C515.1 C516.1 C517.1 C518.1 C519.1 C520.1 C521.1 C522.1 C523.1 C524.1 C525.1 C526.1 C527.1 C528.1 D500.3(A) D500.8(A) FB503.2 J500.A1(GND) J500.A12(GND) J500.B1(GND) J500.B12(GND) J501.1(GND) J501.3(GND) J501.5(GND) J501.7(GND) J501.9(GND) J501.11(GND) J501.13(GND) R500.1 R501.2 R502.1 R504.2 R505.2 R506.2 R508.1 U500.2(GND) U501.4(AGND) U501.9(AGND) U501.10(GND) U501.11(GND) U501.22(GND) U501.23(GND) U501.35(GND) U501.36(GND) U501.41(AGND) U501.42(TEST) U501.47(GND) U501.48(GND) U501.PAD U502.2(GND) U503.2(GND) U503.5(DIR) U504.2(GND) U505.5(VSS) Y500.2(CASE) Y500.4(CASE)
FT232_VCCD: C500.2 C503.2 C507.2 C508.2 C509.2 C513.2 C514.2 C515.2 C519.2 C525.2 C527.2 FB500.1 FB501.1 R503.2 R507.2 R510.2 U500.1(Vcca) U500.5(DIR) U501.12(VCCIO) U501.24(VCCIO) U501.39(VCCD) U501.46(VCCIO) U502.1(Vcca) U502.5(DIR) U503.1(Vcca) U504.1(Vcca) U504.5(DIR) U505.8(VCC)
FT232_VREGIN: C511.2 C512.2 FB502.1 U501.40(VREGIN)
EECLK: R507.1 U501.44(EECLK) U505.2(CLK)
EECS: R508.2 U501.45(EECS) U505.1(CS)
EEDATA: R509.1 U501.43(EEDATA) U505.3(DI)
EEPROM_DO: R509.2 R510.1 U505.4(DO)
FPGA_JTAG_TCK: J501.6(TCK) U500.4(B) ; port JTAG.TCK
FPGA_JTAG_TDI: J501.10(TDI) U502.4(B) ; port JTAG.TDI
FPGA_JTAG_TDO: J501.8(TDO) U503.4(B) ; port JTAG.TDO
FPGA_JTAG_TMS: J501.4(TMS) U504.4(B) ; port JTAG.TMS
FT232_RESET: C521.2 R503.1 U501.34(~{RESET})
FTDI_TCK: U500.3(A) U501.13(ADBUS0_/_TCK_/_SK)
FTDI_TDI: U501.14(ADBUS1_/_TDI_/_DO) U502.3(A)
FTDI_TDO: U501.15(ADBUS2_/_TDO_/_DI) U503.3(A)
FTDI_TMS: U501.16(ADBUS3_/_TMS_/_CS) U504.3(A)
USB_DN: D500.5,6(K) J500.A7(DN1) J500.B7(DN2) U501.6(DM)
USB_DP: D500.4,7(K) J500.A6(DP1) J500.B6(DP2) U501.7(DP)
VBUS_C: C510.2 D500.2,9(K) FB502.2 J500.A4(VBUS) J500.A9(VBUS) J500.B4(VBUS) J500.B9(VBUS)
VCCA: C518.2 U501.37(VCCA)
VCORE: C517.2 U501.38(VCORE)
NetC501_2: C501.2 C502.2 FB500.2 U501.8(VPLL)
NetC505_2: C505.2 C506.2 FB501.2 U501.3(VPHY)
NetC522_2: C522.2 FB503.1 J500.M1(SHELL) J500.M2(SHELL) J500.M3(SHELL) J500.M4(SHELL) R504.1 R505.1 R506.1
NetC523_2: C523.2 U501.1(OSCI) Y500.1(OSC1)
NetC524_2: C524.2 U501.2(OSCO) Y500.3(OSC2)
NetJ500_A5: J500.A5(CC1) R500.2
NetJ500_B5: J500.B5(CC2) R501.1
NetR502_2: R502.2 U501.5(REF)

Not connected (* = marked no-connect by the designer): D500 1,10(K)*; J500 A8(SBU1)* B8(SBU2)*; J501 12(NC)* 14(NC); U501 17(ADBUS4_/_GPIOL0)* 18(ADBUS5_/_GPIOL1)* 19(ADBUS6_/_GPIOL2)* 20(ADBUS7_/_GPIOL3)* 21(ACBUS0_/_GPIOH0)* 25(ACBUS1_/_GPIOH1)* 26(ACBUS2_/_GPIOH2)* 27(ACBUS3_/_GPIOH3)* 28(ACBUS4_/_GPIOH4)* 29(ACBUS5_/_GPIOH5)* 30(ACBUS6_/_GPIOH6)* 31(ACBUS7_/_GPIOH7)* 32(ACBUS8)* 33(ACBUS9)*; U505 6(NC)* 7(NC)*

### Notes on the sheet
- (near C502) USB JTAG
- Level Shifters
- JTAG
- USB Type C Connector
- EEPROM
- JTAG Connector
- Title
- Size:
- Date:
- C
- Number:
- Time:
- Revision:
- Sheet
- of

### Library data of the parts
C500 = 000824: Partnumber: 000824; manufacturer: Taiyo Yuden; ValueFloat: 4.7E-6; x_tolerance: 20
C501 C505 C511 C513 = 000824: Ceramic capacitor; Manufacturer: Taiyo Yuden; partnumber: 000824; Description 2: 0402, 6.3V; ValueFloat: 4.7E-6; Tolerance (%): 20; x_lifecycle_status: Production
C502-C504 C506-C509 C512 C514-C520 C525-C527 = 000070: as C33 on sheet BRK8305
C510 C521 = 000295: Ceramic Capacitor; Partnumber: 000295; Manufacturer: Kemet; ValueFloat: 1E-8; Tolerance (%): 10; Description 2: SM-0402, 10%, 16V, X5R
C522 C528 = 000070: as C37 on sheet BRK8305
C523 C524 = 001640: Ceramic capacitor; Partnumber: 001640; Manufacturer: Kemet; ValueFloat: 1.8E-11; Tolerance (%): 5; Description 2: SM-0402, 5%, 50v, C0G
D500 = 002405: 4 channel TVS diode array; Manufacturer: Diodes Incorporated; PartNumber: 002405; Class I: Discrete; Class II: Diode - Zener; Description 2: USB, TVS
FB500-FB502 = 000569: Ferrite bead; Partnumber: 000569; Manufacturer: Steward; Description 2: SM-0603, 1 A, 600 ohm at 100 MHz
FB503 = 000783: Ferrite Chip; Manufacturer: Murata; partnumber: 000783; Description 2: 220 OHM 2000MA 0805
J500 = 002404: USB 2.0 Type-C receptacle vertical-mount; Partnumber: 002404; Manufacturer: GCT; Description 2: Surface-mount, Vertical-mount
J501 = 000541: 2mm header, shrouded; Manufacturer: Molex; partnumber: 000541; Description 2: Dual-row, 14-pos, Xilinx JTAG compatible
R500 R501 = 001919: Thick-film resistor; Partnumber: 001919; Manufacturer: Vishay; ValueFloat: 5100; Tolerance (%): 1; Description 2: SM-0402, 1%, 1/16W
R502 = 000826: Thick-film resistor; Partnumber: 000826; Manufacturer: Vishay; ValueFloat: 12000; Tolerance (%): 1; Description 2: SM-0402, 1%, 1/16W
R503 R510 = 001521: Thick-film resistor; Partnumber: 001521; Manufacturer: Vishay; ValueFloat: 10000; Tolerance (%): 1; Description 2: SM-0402, 1%, 1/16W
R504-R506 = 000755: Thick-film resistor; Manufacturer: Vishay; partnumber: 000755; Description 2: SM-0402, 1%, 1/16W; Tolerance (%): 1
R507 R508 = 001070: as R1 on sheet BRK8305
R509 = 001162: Thick-film resistor; Partnumber: 001162; Manufacturer: Vishay; ValueFloat: 2000; Tolerance (%): 1; Description 2: SM-0402, 1%, 1/16W
U500 U502-U504 = 002400: Level Translator, 0.65V - 3.6V, Direction Control; Partnumber: 002400; Manufacturer: Texas Instruments; Description 2: Single Bit, Dual Supplies, SOT23-6
U501 = 002398: Partnumber: 002398; manufacturer: FTDI
U505 = 002441: Partnumber: 002441; manufacturer: Opal Kelly Incorporated
Y500 = 002402: Crystal; Partnumber: 002402; Manufacturer: Abracon; Description 2: 12.0 MHz, +/- 50ppm, 3.2mm x 2.5mm, 18 pF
